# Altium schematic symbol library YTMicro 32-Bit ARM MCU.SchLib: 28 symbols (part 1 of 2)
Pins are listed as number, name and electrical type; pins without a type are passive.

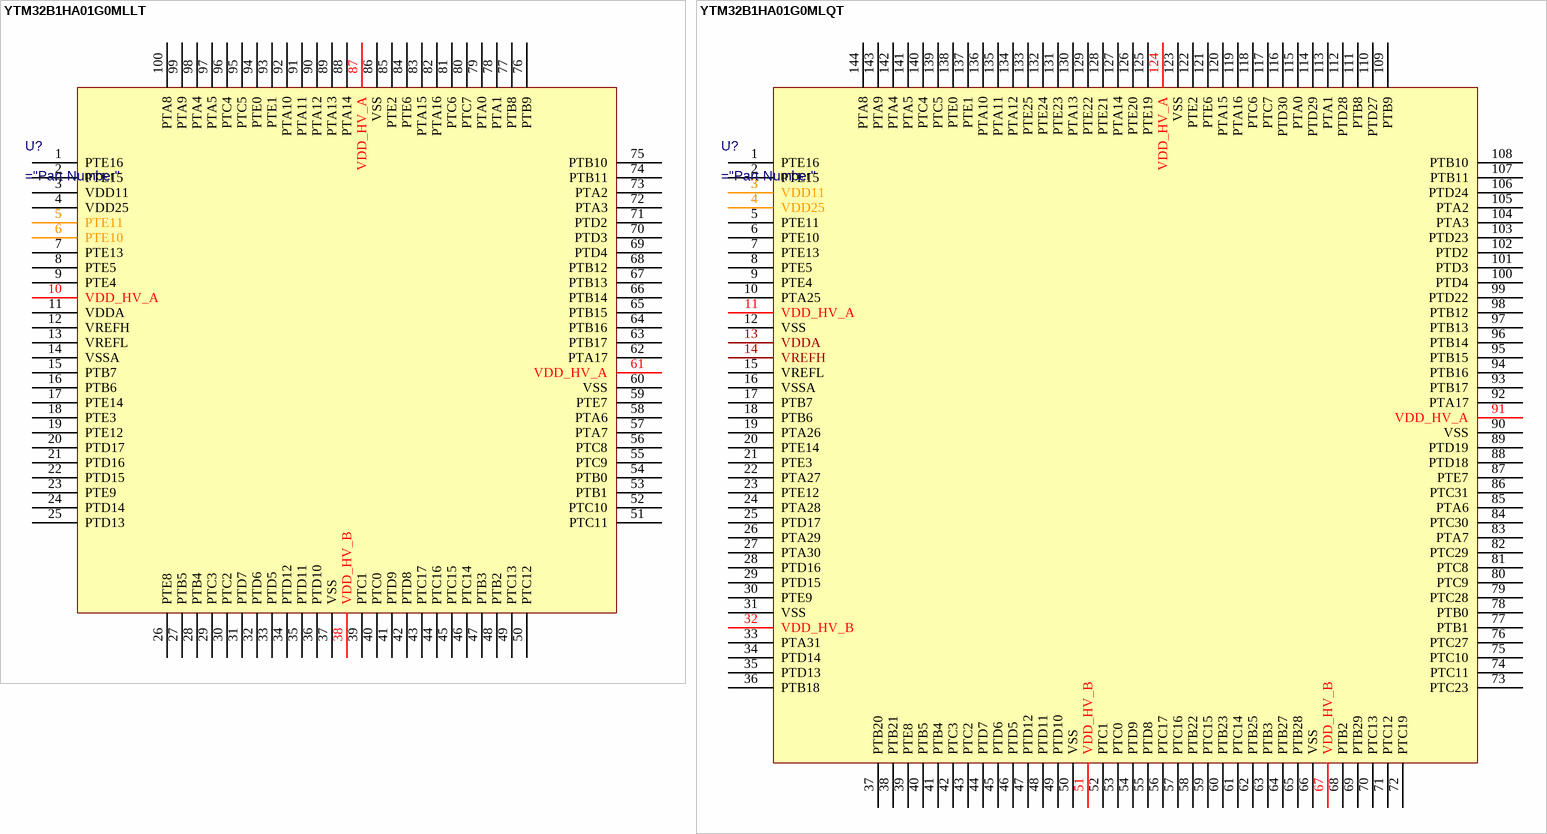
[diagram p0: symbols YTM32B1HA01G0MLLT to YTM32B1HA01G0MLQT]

## YTM32B1HA01G0MLLT
designator U?
B1H family  32-bit ARM Cortex-M7 MCU with Lockstep, 2M flash and 256K SRAM, LQFP-100 package
footprint LQFP100 14x14_M
pins: 1 PTE16, 2 PTE15, 3 VDD11, 4 VDD25, 5 PTE11, 6 PTE10, 7 PTE13, 8 PTE5, 9 PTE4, 10 VDD_HV_A, 11 VDDA, 12 VREFH, 13 VREFL, 14 VSSA, 15 PTB7, 16 PTB6, 17 PTE14, 18 PTE3, 19 PTE12, 20 PTD17, 21 PTD16, 22 PTD15, 23 PTE9, 24 PTD14, 25 PTD13, 26 PTE8, 27 PTB5, 28 PTB4, 29 PTC3, 30 PTC2, 31 PTD7, 32 PTD6, 33 PTD5, 34 PTD12, 35 PTD11, 36 PTD10, 37 VSS, 38 VDD_HV_B, 39 PTC1, 40 PTC0, 41 PTD9, 42 PTD8, 43 PTC17, 44 PTC16, 45 PTC15, 46 PTC14, 47 PTB3, 48 PTB2, 49 PTC13, 50 PTC12, 51 PTC11, 52 PTC10, 53 PTB1, 54 PTB0, 55 PTC9, 56 PTC8, 57 PTA7, 58 PTA6, 59 PTE7, 60 VSS, 61 VDD_HV_A, 62 PTA17, 63 PTB17, 64 PTB16, 65 PTB15, 66 PTB14, 67 PTB13, 68 PTB12, 69 PTD4, 70 PTD3, 71 PTD2, 72 PTA3, 73 PTA2, 74 PTB11, 75 PTB10, 76 PTB9, 77 PTB8, 78 PTA1, 79 PTA0, 80 PTC7, 81 PTC6, 82 PTA16, 83 PTA15, 84 PTE6, 85 PTE2, 86 VSS, 87 VDD_HV_A, 88 PTA14, 89 PTA13, 90 PTA12, 91 PTA11, 92 PTA10, 93 PTE1, 94 PTE0, 95 PTC5, 96 PTC4, 97 PTA5, 98 PTA4, 99 PTA9, 100 PTA8

## YTM32B1HA01G0MLQT
designator U?
B1H family  32-bit ARM Cortex-M7 MCU with Lockstep, 2M flash and 256K SRAM, LQFP-144 package
footprint LQFP144 (144-Pin Thin Quad Flat Pack 0.5 mm Pitch, IPC Medium Density)
pins: 1 PTE16, 2 PTE15, 3 VDD11, 4 VDD25, 5 PTE11, 6 PTE10, 7 PTE13, 8 PTE5, 9 PTE4, 10 PTA25, 11 VDD_HV_A, 12 VSS, 13 VDDA, 14 VREFH, 15 VREFL, 16 VSSA, 17 PTB7, 18 PTB6, 19 PTA26, 20 PTE14, 21 PTE3, 22 PTA27, 23 PTE12, 24 PTA28, 25 PTD17, 26 PTA29, 27 PTA30, 28 PTD16, 29 PTD15, 30 PTE9, 31 VSS, 32 VDD_HV_B, 33 PTA31, 34 PTD14, 35 PTD13, 36 PTB18, 37 PTB20, 38 PTB21, 39 PTE8, 40 PTB5, 41 PTB4, 42 PTC3, 43 PTC2, 44 PTD7, 45 PTD6, 46 PTD5, 47 PTD12, 48 PTD11, 49 PTD10, 50 VSS, 51 VDD_HV_B, 52 PTC1, 53 PTC0, 54 PTD9, 55 PTD8, 56 PTC17, 57 PTC16, 58 PTB22, 59 PTC15, 60 PTB23, 61 PTC14, 62 PTB25, 63 PTB3, 64 PTB27, 65 PTB28, 66 VSS, 67 VDD_HV_B, 68 PTB2, 69 PTB29, 70 PTC13, 71 PTC12, 72 PTC19, 73 PTC23, 74 PTC11, 75 PTC10, 76 PTC27, 77 PTB1, 78 PTB0, 79 PTC28, 80 PTC9, 81 PTC8, 82 PTC29, 83 PTA7, 84 PTC30, 85 PTA6, 86 PTC31, 87 PTE7, 88 PTD18, 89 PTD19, 90 VSS, 91 VDD_HV_A, 92 PTA17, 93 PTB17, 94 PTB16, 95 PTB15, 96 PTB14, 97 PTB13, 98 PTB12, 99 PTD22, 100 PTD4, 101 PTD3, 102 PTD2, 103 PTD23, 104 PTA3, 105 PTA2, 106 PTD24, 107 PTB11, 108 PTB10, 109 PTB9, 110 PTD27, 111 PTB8, 112 PTD28, 113 PTA1, 114 PTD29, 115 PTA0, 116 PTD30, 117 PTC7, 118 PTC6, 119 PTA16, 120 PTA15, 121 PTE6, 122 PTE2, 123 VSS, 124 VDD_HV_A, 125 PTE19, 126 PTE20, 127 PTA14, 128 PTE21, 129 PTE22, 130 PTA13, 131 PTE23, 132 PTE24, 133 PTE25, 134 PTA12, 135 PTA11, 136 PTA10, 137 PTE1, 138 PTE0, 139 PTC5, 140 PTC4, 141 PTA5, 142 PTA4, 143 PTA9, 144 PTA8

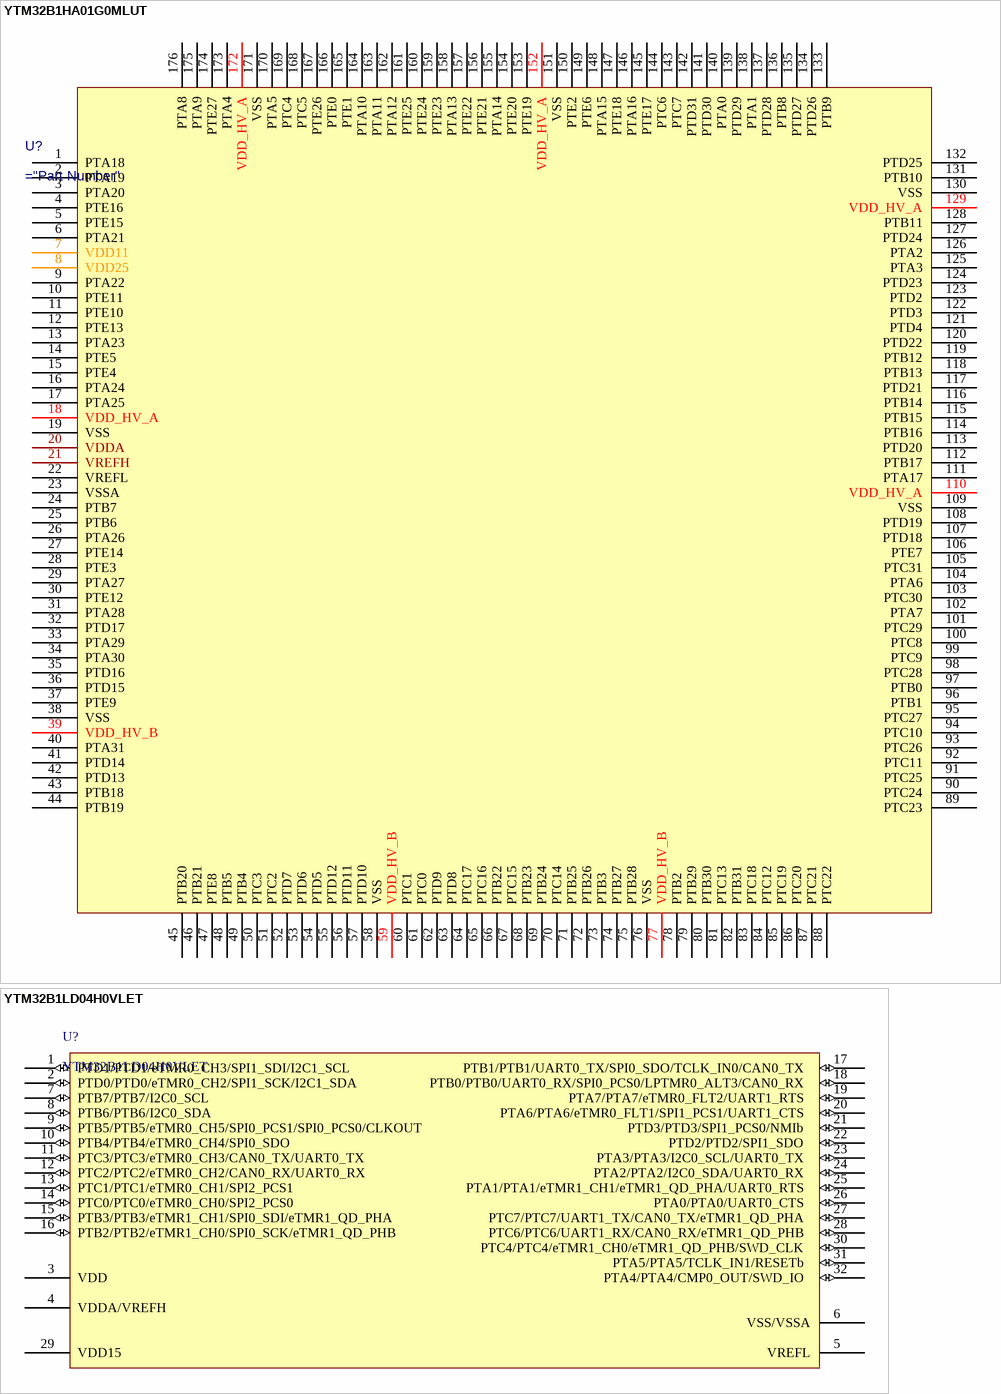
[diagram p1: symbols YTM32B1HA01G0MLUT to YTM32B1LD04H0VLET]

## YTM32B1HA01G0MLUT
designator U?
B1H family  32-bit ARM Cortex-M7 MCU with Lockstep, 2M flash and 256K SRAM, LQFP-176 package
footprint LQFP_176 (LQFP, 176-Leads, Body 26.4x26.4mm (max), Pitch 0.50mm, IPC Medium Density)
pins: 1 PTA18, 2 PTA19, 3 PTA20, 4 PTE16, 5 PTE15, 6 PTA21, 7 VDD11, 8 VDD25, 9 PTA22, 10 PTE11, 11 PTE10, 12 PTE13, 13 PTA23, 14 PTE5, 15 PTE4, 16 PTA24, 17 PTA25, 18 VDD_HV_A, 19 VSS, 20 VDDA, 21 VREFH, 22 VREFL, 23 VSSA, 24 PTB7, 25 PTB6, 26 PTA26, 27 PTE14, 28 PTE3, 29 PTA27, 30 PTE12, 31 PTA28, 32 PTD17, 33 PTA29, 34 PTA30, 35 PTD16, 36 PTD15, 37 PTE9, 38 VSS, 39 VDD_HV_B, 40 PTA31, 41 PTD14, 42 PTD13, 43 PTB18, 44 PTB19, 45 PTB20, 46 PTB21, 47 PTE8, 48 PTB5, 49 PTB4, 50 PTC3, 51 PTC2, 52 PTD7, 53 PTD6, 54 PTD5, 55 PTD12, 56 PTD11, 57 PTD10, 58 VSS, 59 VDD_HV_B, 60 PTC1, 61 PTC0, 62 PTD9, 63 PTD8, 64 PTC17, 65 PTC16, 66 PTB22, 67 PTC15, 68 PTB23, 69 PTB24, 70 PTC14, 71 PTB25, 72 PTB26, 73 PTB3, 74 PTB27, 75 PTB28, 76 VSS, 77 VDD_HV_B, 78 PTB2, 79 PTB29, 80 PTB30, 81 PTC13, 82 PTB31, 83 PTC18, 84 PTC12, 85 PTC19, 86 PTC20, 87 PTC21, 88 PTC22, 89 PTC23, 90 PTC24, 91 PTC25, 92 PTC11, 93 PTC26, 94 PTC10, 95 PTC27, 96 PTB1, 97 PTB0, 98 PTC28, 99 PTC9, 100 PTC8, 101 PTC29, 102 PTA7, 103 PTC30, 104 PTA6, 105 PTC31, 106 PTE7, 107 PTD18, 108 PTD19, 109 VSS, 110 VDD_HV_A, 111 PTA17, 112 PTB17, 113 PTD20, 114 PTB16, 115 PTB15, 116 PTB14, 117 PTD21, 118 PTB13, 119 PTB12, 120 PTD22, 121 PTD4, 122 PTD3, 123 PTD2, 124 PTD23, 125 PTA3, 126 PTA2, 127 PTD24, 128 PTB11, 129 VDD_HV_A, 130 VSS, 131 PTB10, 132 PTD25, 133 PTB9, 134 PTD26, 135 PTD27, 136 PTB8, 137 PTD28, 138 PTA1, 139 PTD29, 140 PTA0, 141 PTD30, 142 PTD31, 143 PTC7, 144 PTC6, 145 PTE17, 146 PTA16, 147 PTE18, 148 PTA15, 149 PTE6, 150 PTE2, 151 VSS, 152 VDD_HV_A, 153 PTE19, 154 PTE20, 155 PTA14, 156 PTE21, 157 PTE22, 158 PTA13, 159 PTE23, 160 PTE24, 161 PTE25, 162 PTA12, 163 PTA11, 164 PTA10, 165 PTE1, 166 PTE0, 167 PTE26, 168 PTC5, 169 PTC4, 170 PTA5, 171 VSS, 172 VDD_HV_A, 173 PTA4, 174 PTE27, 175 PTA9, 176 PTA8

## YTM32B1LD04H0VLET
designator U?
B1L family  32-bit ARM Cortex-M0+ MCU with 64K flash and 8K SRAM, LQFP-32 package
footprint LQFP32 7X7_L
footprint LQFP32 7X7_M
footprint LQFP32 7X7_N
pins: 1 PTD1/PTD1/eTMR0_CH3/SPI1_SDI/I2C1_SCL   (io), 2 PTD0/PTD0/eTMR0_CH2/SPI1_SCK/I2C1_SDA   (io), 3 VDD (power), 4 VDDA/VREFH (power), 5 VREFL (power), 6 VSS/VSSA (power), 7 PTB7/PTB7/I2C0_SCL  (io), 8 PTB6/PTB6/I2C0_SDA   (io), 9 PTB5/PTB5/eTMR0_CH5/SPI0_PCS1/SPI0_PCS0/CLKOUT   (io), 10 PTB4/PTB4/eTMR0_CH4/SPI0_SDO   (io), 11 PTC3/PTC3/eTMR0_CH3/CAN0_TX/UART0_TX   (io), 12 PTC2/PTC2/eTMR0_CH2/CAN0_RX/UART0_RX   (io), 13 PTC1/PTC1/eTMR0_CH1/SPI2_PCS1   (io), 14 PTC0/PTC0/eTMR0_CH0/SPI2_PCS0   (io), 15 PTB3/PTB3/eTMR1_CH1/SPI0_SDI/eTMR1_QD_PHA   (io), 16 PTB2/PTB2/eTMR1_CH0/SPI0_SCK/eTMR1_QD_PHB   (io), 17 PTB1/PTB1/UART0_TX/SPI0_SDO/TCLK_IN0/CAN0_TX   (io), 18 PTB0/PTB0/UART0_RX/SPI0_PCS0/LPTMR0_ALT3/CAN0_RX   (io), 19 PTA7/PTA7/eTMR0_FLT2/UART1_RTS   (io), 20 PTA6/PTA6/eTMR0_FLT1/SPI1_PCS1/UART1_CTS   (io), 21 PTD3/PTD3/SPI1_PCS0/NMIb   (io), 22 PTD2/PTD2/SPI1_SDO   (io), 23 PTA3/PTA3/I2C0_SCL/UART0_TX   (io), 24 PTA2/PTA2/I2C0_SDA/UART0_RX   (io), 25 PTA1/PTA1/eTMR1_CH1/eTMR1_QD_PHA/UART0_RTS   (io), 26 PTA0/PTA0/UART0_CTS   (io), 27 PTC7/PTC7/UART1_TX/CAN0_TX/eTMR1_QD_PHA   (io), 28 PTC6/PTC6/UART1_RX/CAN0_RX/eTMR1_QD_PHB   (io), 29 VDD15 (power), 30 PTC4/PTC4/eTMR1_CH0/eTMR1_QD_PHB/SWD_CLK   (io), 31 PTA5/PTA5/TCLK_IN1/RESETb   (io), 32 PTA4/PTA4/CMP0_OUT/SWD_IO   (io)

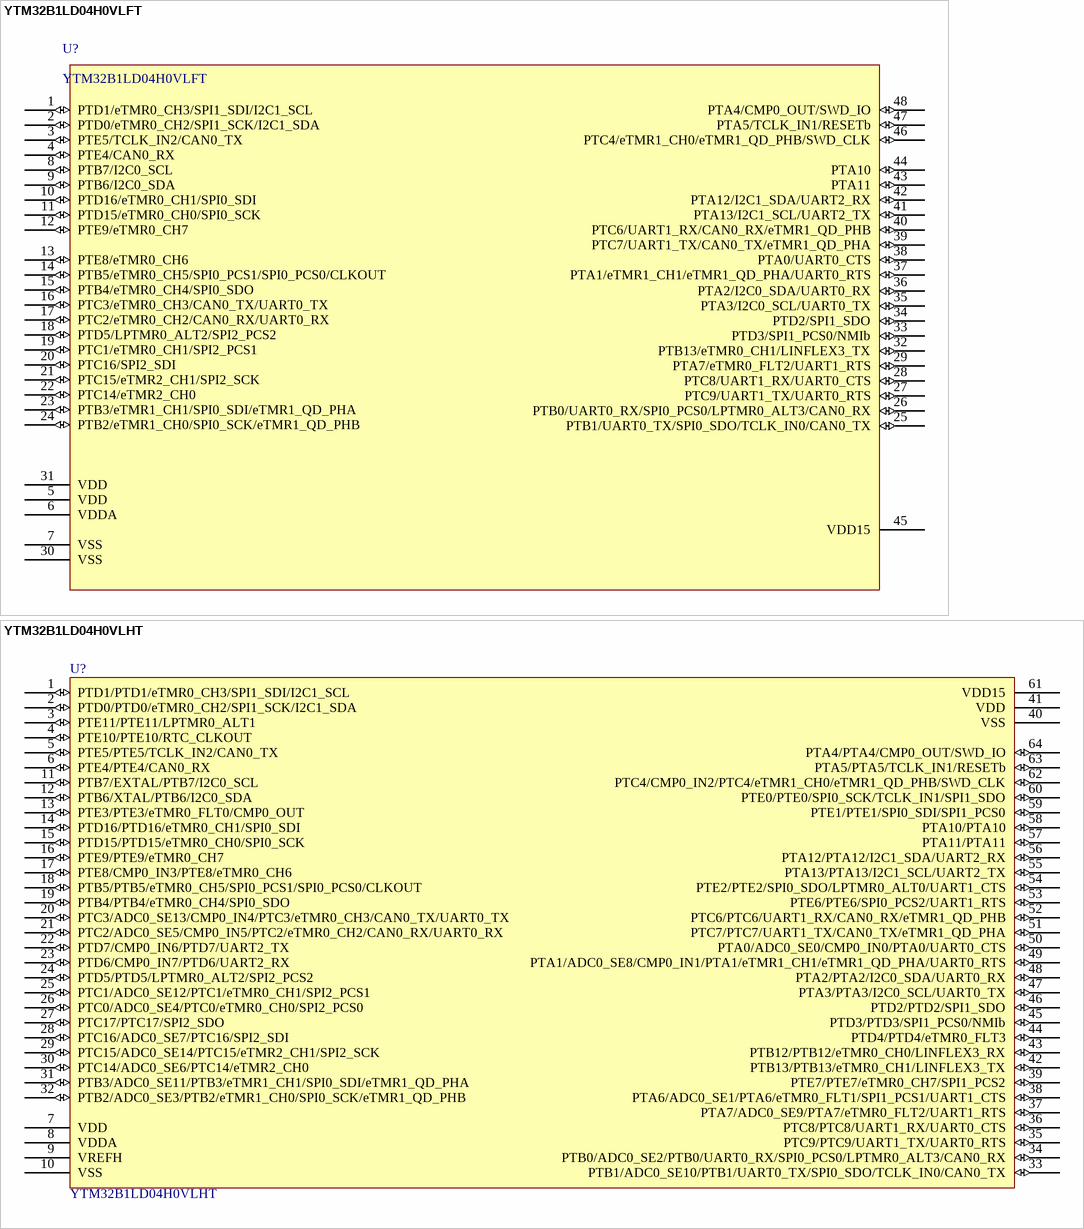
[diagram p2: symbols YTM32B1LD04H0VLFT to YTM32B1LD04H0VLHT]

## YTM32B1LD04H0VLFT
designator U?
B1L family  32-bit ARM Cortex-M0+ MCU with 64K flash and 8K SRAM, LQFP-48 package
footprint LQFP48 7X7_N (48脚，体宽7x7mm，脚距0.5mm)
footprint LQFP48 7X7_M
footprint LQFP48 7X7_L
pins: 1 PTD1/eTMR0_CH3/SPI1_SDI/I2C1_SCL (io), 2 PTD0/eTMR0_CH2/SPI1_SCK/I2C1_SDA (io), 3 PTE5/TCLK_IN2/CAN0_TX (io), 4 PTE4/CAN0_RX (io), 5 VDD (power), 6 VDDA (power), 7 VSS, 8 PTB7/I2C0_SCL (io), 9 PTB6/I2C0_SDA (io), 10 PTD16/eTMR0_CH1/SPI0_SDI (io), 11 PTD15/eTMR0_CH0/SPI0_SCK (io), 12 PTE9/eTMR0_CH7 (io), 13 PTE8/eTMR0_CH6 (io), 14 PTB5/eTMR0_CH5/SPI0_PCS1/SPI0_PCS0/CLKOUT (io), 15 PTB4/eTMR0_CH4/SPI0_SDO (io), 16 PTC3/eTMR0_CH3/CAN0_TX/UART0_TX (io), 17 PTC2/eTMR0_CH2/CAN0_RX/UART0_RX (io), 18 PTD5/LPTMR0_ALT2/SPI2_PCS2 (io), 19 PTC1/eTMR0_CH1/SPI2_PCS1 (io), 20 PTC16/SPI2_SDI (io), 21 PTC15/eTMR2_CH1/SPI2_SCK (io), 22 PTC14/eTMR2_CH0 (io), 23 PTB3/eTMR1_CH1/SPI0_SDI/eTMR1_QD_PHA (io), 24 PTB2/eTMR1_CH0/SPI0_SCK/eTMR1_QD_PHB (io), 25 PTB1/UART0_TX/SPI0_SDO/TCLK_IN0/CAN0_TX (io), 26 PTB0/UART0_RX/SPI0_PCS0/LPTMR0_ALT3/CAN0_RX (io), 27 PTC9/UART1_TX/UART0_RTS (io), 28 PTC8/UART1_RX/UART0_CTS (io), 29 PTA7/eTMR0_FLT2/UART1_RTS (io), 30 VSS, 31 VDD (power), 32 PTB13/eTMR0_CH1/LINFLEX3_TX (io), 33 PTD3/SPI1_PCS0/NMIb (io), 34 PTD2/SPI1_SDO (io), 35 PTA3/I2C0_SCL/UART0_TX (io), 36 PTA2/I2C0_SDA/UART0_RX (io), 37 PTA1/eTMR1_CH1/eTMR1_QD_PHA/UART0_RTS (io), 38 PTA0/UART0_CTS (io), 39 PTC7/UART1_TX/CAN0_TX/eTMR1_QD_PHA (io), 40 PTC6/UART1_RX/CAN0_RX/eTMR1_QD_PHB (io), 41 PTA13/I2C1_SCL/UART2_TX (io), 42 PTA12/I2C1_SDA/UART2_RX (io), 43 PTA11 (io), 44 PTA10 (io), 45 VDD15 (power), 46 PTC4/eTMR1_CH0/eTMR1_QD_PHB/SWD_CLK (io), 47 PTA5/TCLK_IN1/RESETb (io), 48 PTA4/CMP0_OUT/SWD_IO (io)

## YTM32B1LD04H0VLHT
designator U?
B1L family  32-bit ARM Cortex-M0+ MCU with 128K flash and 8K SRAM, LQFP-64 package
footprint LQFP64 10x10_N
footprint LQFP64 10x10_L
footprint LQFP64 10x10_M
pins: 1 PTD1/PTD1/eTMR0_CH3/SPI1_SDI/I2C1_SCL (io), 2 PTD0/PTD0/eTMR0_CH2/SPI1_SCK/I2C1_SDA (io), 3 PTE11/PTE11/LPTMR0_ALT1 (io), 4 PTE10/PTE10/RTC_CLKOUT (io), 5 PTE5/PTE5/TCLK_IN2/CAN0_TX (io), 6 PTE4/PTE4/CAN0_RX (io), 7 VDD (power), 8 VDDA (power), 9 VREFH (power), 10 VSS (power), 11 PTB7/EXTAL/PTB7/I2C0_SCL (io), 12 PTB6/XTAL/PTB6/I2C0_SDA (io), 13 PTE3/PTE3/eTMR0_FLT0/CMP0_OUT (io), 14 PTD16/PTD16/eTMR0_CH1/SPI0_SDI (io), 15 PTD15/PTD15/eTMR0_CH0/SPI0_SCK (io), 16 PTE9/PTE9/eTMR0_CH7 (io), 17 PTE8/CMP0_IN3/PTE8/eTMR0_CH6 (io), 18 PTB5/PTB5/eTMR0_CH5/SPI0_PCS1/SPI0_PCS0/CLKOUT (io), 19 PTB4/PTB4/eTMR0_CH4/SPI0_SDO (io), 20 PTC3/ADC0_SE13/CMP0_IN4/PTC3/eTMR0_CH3/CAN0_TX/UART0_TX (io), 21 PTC2/ADC0_SE5/CMP0_IN5/PTC2/eTMR0_CH2/CAN0_RX/UART0_RX (io), 22 PTD7/CMP0_IN6/PTD7/UART2_TX (io), 23 PTD6/CMP0_IN7/PTD6/UART2_RX (io), 24 PTD5/PTD5/LPTMR0_ALT2/SPI2_PCS2 (io), 25 PTC1/ADC0_SE12/PTC1/eTMR0_CH1/SPI2_PCS1 (io), 26 PTC0/ADC0_SE4/PTC0/eTMR0_CH0/SPI2_PCS0 (io), 27 PTC17/PTC17/SPI2_SDO (io), 28 PTC16/ADC0_SE7/PTC16/SPI2_SDI (io), 29 PTC15/ADC0_SE14/PTC15/eTMR2_CH1/SPI2_SCK (io), 30 PTC14/ADC0_SE6/PTC14/eTMR2_CH0 (io), 31 PTB3/ADC0_SE11/PTB3/eTMR1_CH1/SPI0_SDI/eTMR1_QD_PHA (io), 32 PTB2/ADC0_SE3/PTB2/eTMR1_CH0/SPI0_SCK/eTMR1_QD_PHB (io), 33 PTB1/ADC0_SE10/PTB1/UART0_TX/SPI0_SDO/TCLK_IN0/CAN0_TX (io), 34 PTB0/ADC0_SE2/PTB0/UART0_RX/SPI0_PCS0/LPTMR0_ALT3/CAN0_RX (io), 35 PTC9/PTC9/UART1_TX/UART0_RTS (io), 36 PTC8/PTC8/UART1_RX/UART0_CTS (io), 37 PTA7/ADC0_SE9/PTA7/eTMR0_FLT2/UART1_RTS (io), 38 PTA6/ADC0_SE1/PTA6/eTMR0_FLT1/SPI1_PCS1/UART1_CTS (io), 39 PTE7/PTE7/eTMR0_CH7/SPI1_PCS2 (io), 40 VSS (power), 41 VDD (power), 42 PTB13/PTB13/eTMR0_CH1/LINFLEX3_TX (io), 43 PTB12/PTB12/eTMR0_CH0/LINFLEX3_RX (io), 44 PTD4/PTD4/eTMR0_FLT3 (io), 45 PTD3/PTD3/SPI1_PCS0/NMIb (io), 46 PTD2/PTD2/SPI1_SDO (io), 47 PTA3/PTA3/I2C0_SCL/UART0_TX (io), 48 PTA2/PTA2/I2C0_SDA/UART0_RX (io), 49 PTA1/ADC0_SE8/CMP0_IN1/PTA1/eTMR1_CH1/eTMR1_QD_PHA/UART0_RTS (io), 50 PTA0/ADC0_SE0/CMP0_IN0/PTA0/UART0_CTS (io), 51 PTC7/PTC7/UART1_TX/CAN0_TX/eTMR1_QD_PHA (io), 52 PTC6/PTC6/UART1_RX/CAN0_RX/eTMR1_QD_PHB (io), 53 PTE6/PTE6/SPI0_PCS2/UART1_RTS (io), 54 PTE2/PTE2/SPI0_SDO/LPTMR0_ALT0/UART1_CTS (io), 55 PTA13/PTA13/I2C1_SCL/UART2_TX (io), 56 PTA12/PTA12/I2C1_SDA/UART2_RX (io), 57 PTA11/PTA11 (io), 58 PTA10/PTA10 (io), 59 PTE1/PTE1/SPI0_SDI/SPI1_PCS0 (io), 60 PTE0/PTE0/SPI0_SCK/TCLK_IN1/SPI1_SDO (io), 61 VDD15 (power), 62 PTC4/CMP0_IN2/PTC4/eTMR1_CH0/eTMR1_QD_PHB/SWD_CLK (io), 63 PTA5/PTA5/TCLK_IN1/RESETb (io), 64 PTA4/PTA4/CMP0_OUT/SWD_IO (io)

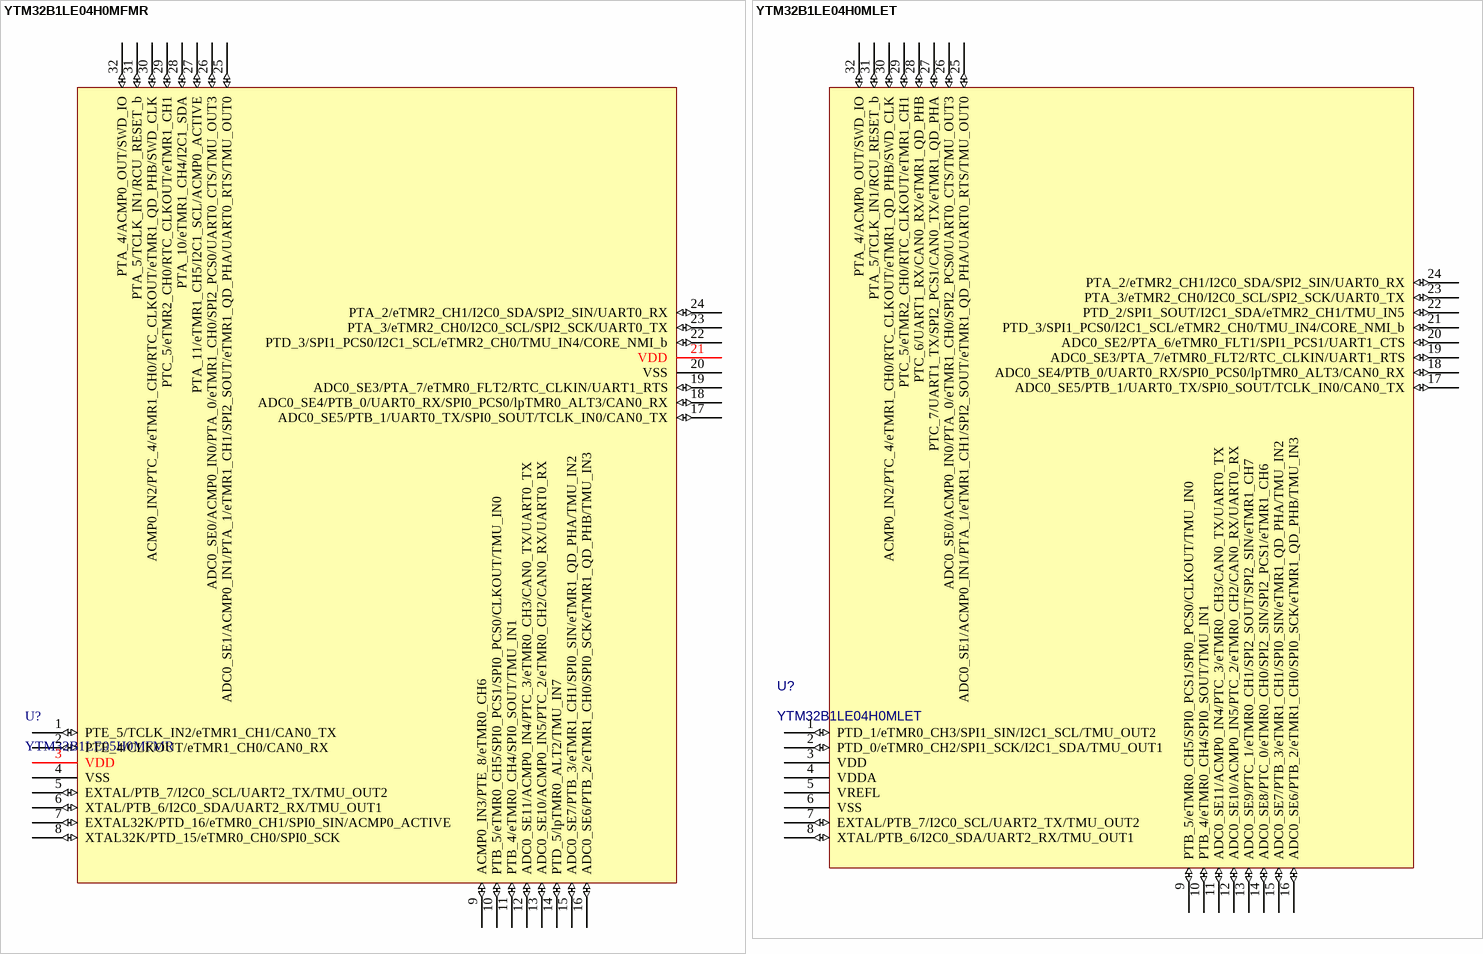
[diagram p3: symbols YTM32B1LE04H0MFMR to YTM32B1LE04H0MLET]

## YTM32B1LE04H0MFMR
designator U?, comment YTM32B1LE05H0MFMR
B1L family  32-bit ARM Cortex-M0+ MCU with 128K flash and 16K SRAM, QFN-32 package
footprint QFN32
pins: 1 PTE_5/TCLK_IN2/eTMR1_CH1/CAN0_TX (io), 2 PTE_4/CLKOUT/eTMR1_CH0/CAN0_RX (io), 3 VDD, 4 VSS, 5 EXTAL/PTB_7/I2C0_SCL/UART2_TX/TMU_OUT2 (io), 6 XTAL/PTB_6/I2C0_SDA/UART2_RX/TMU_OUT1 (io), 7 EXTAL32K/PTD_16/eTMR0_CH1/SPI0_SIN/ACMP0_ACTIVE (io), 8 XTAL32K/PTD_15/eTMR0_CH0/SPI0_SCK (io), 9 ACMP0_IN3/PTE_8/eTMR0_CH6 (io), 10 PTB_5/eTMR0_CH5/SPI0_PCS1/SPI0_PCS0/CLKOUT/TMU_IN0 (io), 11 PTB_4/eTMR0_CH4/SPI0_SOUT/TMU_IN1 (io), 12 ADC0_SE11/ACMP0_IN4/PTC_3/eTMR0_CH3/CAN0_TX/UART0_TX (io), 13 ADC0_SE10/ACMP0_IN5/PTC_2/eTMR0_CH2/CAN0_RX/UART0_RX (io), 14 PTD_5/lpTMR0_ALT2/TMU_IN7 (io), 15 ADC0_SE7/PTB_3/eTMR1_CH1/SPI0_SIN/eTMR1_QD_PHA/TMU_IN2 (io), 16 ADC0_SE6/PTB_2/eTMR1_CH0/SPI0_SCK/eTMR1_QD_PHB/TMU_IN3 (io), 17 ADC0_SE5/PTB_1/UART0_TX/SPI0_SOUT/TCLK_IN0/CAN0_TX (io), 18 ADC0_SE4/PTB_0/UART0_RX/SPI0_PCS0/lpTMR0_ALT3/CAN0_RX (io), 19 ADC0_SE3/PTA_7/eTMR0_FLT2/RTC_CLKIN/UART1_RTS (io), 20 VSS, 21 VDD, 22 PTD_3/SPI1_PCS0/I2C1_SCL/eTMR2_CH0/TMU_IN4/CORE_NMI_b (io), 23 PTA_3/eTMR2_CH0/I2C0_SCL/SPI2_SCK/UART0_TX (io), 24 PTA_2/eTMR2_CH1/I2C0_SDA/SPI2_SIN/UART0_RX (io), 25 ADC0_SE1/ACMP0_IN1/PTA_1/eTMR1_CH1/SPI2_SOUT/eTMR1_QD_PHA/UART0_RTS/TMU_OUT0 (io), 26 ADC0_SE0/ACMP0_IN0/PTA_0/eTMR1_CH0/SPI2_PCS0/UART0_CTS/TMU_OUT3 (io), 27 PTA_11/eTMR1_CH5/I2C1_SCL/ACMP0_ACTIVE (io), 28 PTA_10/eTMR1_CH4/I2C1_SDA (io), 29 PTC_5/eTMR2_CH0/RTC_CLKOUT/eTMR1_CH1 (io), 30 ACMP0_IN2/PTC_4/eTMR1_CH0/RTC_CLKOUT/eTMR1_QD_PHB/SWD_CLK (io), 31 PTA_5/TCLK_IN1/RCU_RESET_b (io), 32 PTA_4/ACMP0_OUT/SWD_IO (io)

## YTM32B1LE04H0MLET
designator U?
B1L family  32-bit ARM Cortex-M0+ MCU with 128K flash and 16K SRAM, LQFP-32 package
footprint LQFP32 7X7_L
footprint LQFP32 7X7_M
footprint LQFP32 7X7_N
pins: 1 PTD_1/eTMR0_CH3/SPI1_SIN/I2C1_SCL/TMU_OUT2 (io), 2 PTD_0/eTMR0_CH2/SPI1_SCK/I2C1_SDA/TMU_OUT1 (io), 3 VDD, 4 VDDA, 5 VREFL, 6 VSS, 7 EXTAL/PTB_7/I2C0_SCL/UART2_TX/TMU_OUT2 (io), 8 XTAL/PTB_6/I2C0_SDA/UART2_RX/TMU_OUT1 (io), 9 PTB_5/eTMR0_CH5/SPI0_PCS1/SPI0_PCS0/CLKOUT/TMU_IN0 (io), 10 PTB_4/eTMR0_CH4/SPI0_SOUT/TMU_IN1 (io), 11 ADC0_SE11/ACMP0_IN4/PTC_3/eTMR0_CH3/CAN0_TX/UART0_TX (io), 12 ADC0_SE10/ACMP0_IN5/PTC_2/eTMR0_CH2/CAN0_RX/UART0_RX (io), 13 ADC0_SE9/PTC_1/eTMR0_CH1/SPI2_SOUT/SPI2_SIN/eTMR1_CH7 (io), 14 ADC0_SE8/PTC_0/eTMR0_CH0/SPI2_SIN/SPI2_PCS1/eTMR1_CH6 (io), 15 ADC0_SE7/PTB_3/eTMR1_CH1/SPI0_SIN/eTMR1_QD_PHA/TMU_IN2 (io), 16 ADC0_SE6/PTB_2/eTMR1_CH0/SPI0_SCK/eTMR1_QD_PHB/TMU_IN3 (io), 17 ADC0_SE5/PTB_1/UART0_TX/SPI0_SOUT/TCLK_IN0/CAN0_TX (io), 18 ADC0_SE4/PTB_0/UART0_RX/SPI0_PCS0/lpTMR0_ALT3/CAN0_RX (io), 19 ADC0_SE3/PTA_7/eTMR0_FLT2/RTC_CLKIN/UART1_RTS (io), 20 ADC0_SE2/PTA_6/eTMR0_FLT1/SPI1_PCS1/UART1_CTS (io), 21 PTD_3/SPI1_PCS0/I2C1_SCL/eTMR2_CH0/TMU_IN4/CORE_NMI_b (io), 22 PTD_2/SPI1_SOUT/I2C1_SDA/eTMR2_CH1/TMU_IN5 (io), 23 PTA_3/eTMR2_CH0/I2C0_SCL/SPI2_SCK/UART0_TX (io), 24 PTA_2/eTMR2_CH1/I2C0_SDA/SPI2_SIN/UART0_RX (io), 25 ADC0_SE1/ACMP0_IN1/PTA_1/eTMR1_CH1/SPI2_SOUT/eTMR1_QD_PHA/UART0_RTS/TMU_OUT0 (io), 26 ADC0_SE0/ACMP0_IN0/PTA_0/eTMR1_CH0/SPI2_PCS0/UART0_CTS/TMU_OUT3 (io), 27 PTC_7/UART1_TX/SPI2_PCS1/CAN0_TX/eTMR1_QD_PHA (io), 28 PTC_6/UART1_RX/CAN0_RX/eTMR1_QD_PHB (io), 29 PTC_5/eTMR2_CH0/RTC_CLKOUT/eTMR1_CH1 (io), 30 ACMP0_IN2/PTC_4/eTMR1_CH0/RTC_CLKOUT/eTMR1_QD_PHB/SWD_CLK (io), 31 PTA_5/TCLK_IN1/RCU_RESET_b (io), 32 PTA_4/ACMP0_OUT/SWD_IO (io)

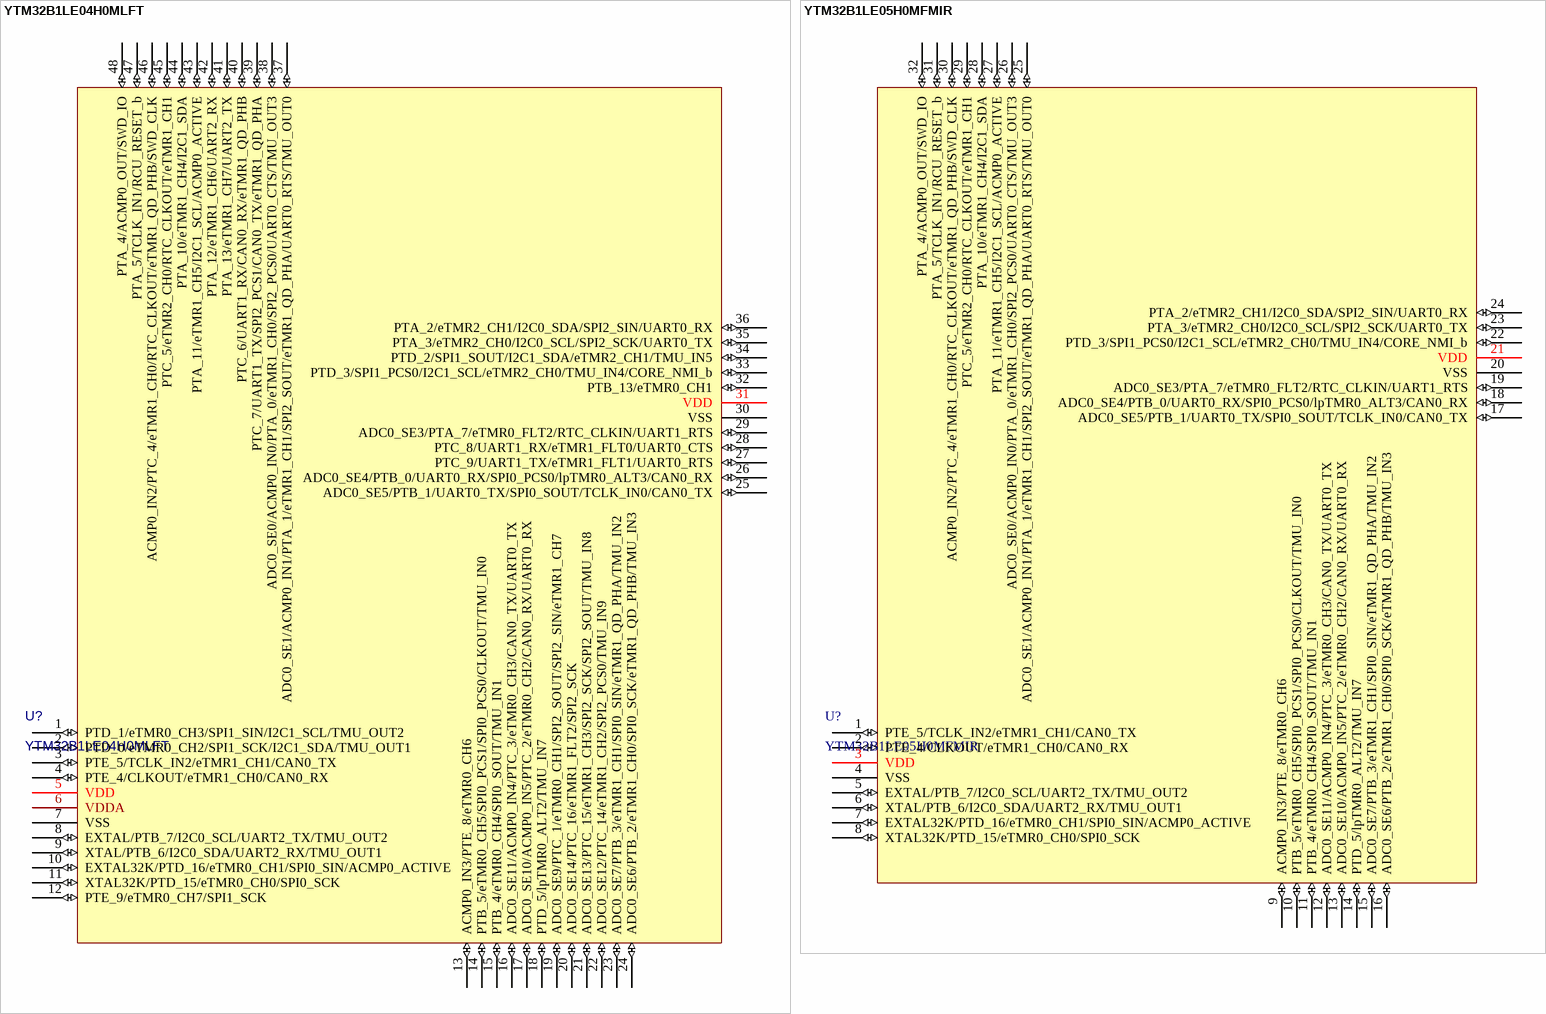
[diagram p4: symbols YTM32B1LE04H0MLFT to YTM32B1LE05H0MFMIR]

## YTM32B1LE04H0MLFT
designator U?
B1L family  32-bit ARM Cortex-M0+ MCU with 128K flash and 16K SRAM, LQFP-48 package
footprint LQFP48 7X7_L
footprint LQFP48 7X7_M
footprint LQFP48 7X7_N
pins: 1 PTD_1/eTMR0_CH3/SPI1_SIN/I2C1_SCL/TMU_OUT2 (io), 2 PTD_0/eTMR0_CH2/SPI1_SCK/I2C1_SDA/TMU_OUT1 (io), 3 PTE_5/TCLK_IN2/eTMR1_CH1/CAN0_TX (io), 4 PTE_4/CLKOUT/eTMR1_CH0/CAN0_RX (io), 5 VDD, 6 VDDA, 7 VSS, 8 EXTAL/PTB_7/I2C0_SCL/UART2_TX/TMU_OUT2 (io), 9 XTAL/PTB_6/I2C0_SDA/UART2_RX/TMU_OUT1 (io), 10 EXTAL32K/PTD_16/eTMR0_CH1/SPI0_SIN/ACMP0_ACTIVE (io), 11 XTAL32K/PTD_15/eTMR0_CH0/SPI0_SCK (io), 12 PTE_9/eTMR0_CH7/SPI1_SCK (io), 13 ACMP0_IN3/PTE_8/eTMR0_CH6 (io), 14 PTB_5/eTMR0_CH5/SPI0_PCS1/SPI0_PCS0/CLKOUT/TMU_IN0 (io), 15 PTB_4/eTMR0_CH4/SPI0_SOUT/TMU_IN1 (io), 16 ADC0_SE11/ACMP0_IN4/PTC_3/eTMR0_CH3/CAN0_TX/UART0_TX (io), 17 ADC0_SE10/ACMP0_IN5/PTC_2/eTMR0_CH2/CAN0_RX/UART0_RX (io), 18 PTD_5/lpTMR0_ALT2/TMU_IN7 (io), 19 ADC0_SE9/PTC_1/eTMR0_CH1/SPI2_SOUT/SPI2_SIN/eTMR1_CH7 (io), 20 ADC0_SE14/PTC_16/eTMR1_FLT2/SPI2_SCK (io), 21 ADC0_SE13/PTC_15/eTMR1_CH3/SPI2_SCK/SPI2_SOUT/TMU_IN8 (io), 22 ADC0_SE12/PTC_14/eTMR1_CH2/SPI2_PCS0/TMU_IN9 (io), 23 ADC0_SE7/PTB_3/eTMR1_CH1/SPI0_SIN/eTMR1_QD_PHA/TMU_IN2 (io), 24 ADC0_SE6/PTB_2/eTMR1_CH0/SPI0_SCK/eTMR1_QD_PHB/TMU_IN3 (io), 25 ADC0_SE5/PTB_1/UART0_TX/SPI0_SOUT/TCLK_IN0/CAN0_TX (io), 26 ADC0_SE4/PTB_0/UART0_RX/SPI0_PCS0/lpTMR0_ALT3/CAN0_RX (io), 27 PTC_9/UART1_TX/eTMR1_FLT1/UART0_RTS (io), 28 PTC_8/UART1_RX/eTMR1_FLT0/UART0_CTS (io), 29 ADC0_SE3/PTA_7/eTMR0_FLT2/RTC_CLKIN/UART1_RTS (io), 30 VSS, 31 VDD, 32 PTB_13/eTMR0_CH1 (io), 33 PTD_3/SPI1_PCS0/I2C1_SCL/eTMR2_CH0/TMU_IN4/CORE_NMI_b (io), 34 PTD_2/SPI1_SOUT/I2C1_SDA/eTMR2_CH1/TMU_IN5 (io), 35 PTA_3/eTMR2_CH0/I2C0_SCL/SPI2_SCK/UART0_TX (io), 36 PTA_2/eTMR2_CH1/I2C0_SDA/SPI2_SIN/UART0_RX (io), 37 ADC0_SE1/ACMP0_IN1/PTA_1/eTMR1_CH1/SPI2_SOUT/eTMR1_QD_PHA/UART0_RTS/TMU_OUT0 (io), 38 ADC0_SE0/ACMP0_IN0/PTA_0/eTMR1_CH0/SPI2_PCS0/UART0_CTS/TMU_OUT3 (io), 39 PTC_7/UART1_TX/SPI2_PCS1/CAN0_TX/eTMR1_QD_PHA (io), 40 PTC_6/UART1_RX/CAN0_RX/eTMR1_QD_PHB (io), 41 PTA_13/eTMR1_CH7/UART2_TX (io), 42 PTA_12/eTMR1_CH6/UART2_RX (io), 43 PTA_11/eTMR1_CH5/I2C1_SCL/ACMP0_ACTIVE (io), 44 PTA_10/eTMR1_CH4/I2C1_SDA (io), 45 PTC_5/eTMR2_CH0/RTC_CLKOUT/eTMR1_CH1 (io), 46 ACMP0_IN2/PTC_4/eTMR1_CH0/RTC_CLKOUT/eTMR1_QD_PHB/SWD_CLK (io), 47 PTA_5/TCLK_IN1/RCU_RESET_b (io), 48 PTA_4/ACMP0_OUT/SWD_IO (io)

## YTM32B1LE05H0MFMIR
designator U?
B1L family  32-bit ARM Cortex-M0+ MCU with 128K flash and 16K SRAM, QFN-32 package, with ISELED support
footprint QFN32
pins: 1 PTE_5/TCLK_IN2/eTMR1_CH1/CAN0_TX (io), 2 PTE_4/CLKOUT/eTMR1_CH0/CAN0_RX (io), 3 VDD, 4 VSS, 5 EXTAL/PTB_7/I2C0_SCL/UART2_TX/TMU_OUT2 (io), 6 XTAL/PTB_6/I2C0_SDA/UART2_RX/TMU_OUT1 (io), 7 EXTAL32K/PTD_16/eTMR0_CH1/SPI0_SIN/ACMP0_ACTIVE (io), 8 XTAL32K/PTD_15/eTMR0_CH0/SPI0_SCK (io), 9 ACMP0_IN3/PTE_8/eTMR0_CH6 (io), 10 PTB_5/eTMR0_CH5/SPI0_PCS1/SPI0_PCS0/CLKOUT/TMU_IN0 (io), 11 PTB_4/eTMR0_CH4/SPI0_SOUT/TMU_IN1 (io), 12 ADC0_SE11/ACMP0_IN4/PTC_3/eTMR0_CH3/CAN0_TX/UART0_TX (io), 13 ADC0_SE10/ACMP0_IN5/PTC_2/eTMR0_CH2/CAN0_RX/UART0_RX (io), 14 PTD_5/lpTMR0_ALT2/TMU_IN7 (io), 15 ADC0_SE7/PTB_3/eTMR1_CH1/SPI0_SIN/eTMR1_QD_PHA/TMU_IN2 (io), 16 ADC0_SE6/PTB_2/eTMR1_CH0/SPI0_SCK/eTMR1_QD_PHB/TMU_IN3 (io), 17 ADC0_SE5/PTB_1/UART0_TX/SPI0_SOUT/TCLK_IN0/CAN0_TX (io), 18 ADC0_SE4/PTB_0/UART0_RX/SPI0_PCS0/lpTMR0_ALT3/CAN0_RX (io), 19 ADC0_SE3/PTA_7/eTMR0_FLT2/RTC_CLKIN/UART1_RTS (io), 20 VSS, 21 VDD, 22 PTD_3/SPI1_PCS0/I2C1_SCL/eTMR2_CH0/TMU_IN4/CORE_NMI_b (io), 23 PTA_3/eTMR2_CH0/I2C0_SCL/SPI2_SCK/UART0_TX (io), 24 PTA_2/eTMR2_CH1/I2C0_SDA/SPI2_SIN/UART0_RX (io), 25 ADC0_SE1/ACMP0_IN1/PTA_1/eTMR1_CH1/SPI2_SOUT/eTMR1_QD_PHA/UART0_RTS/TMU_OUT0 (io), 26 ADC0_SE0/ACMP0_IN0/PTA_0/eTMR1_CH0/SPI2_PCS0/UART0_CTS/TMU_OUT3 (io), 27 PTA_11/eTMR1_CH5/I2C1_SCL/ACMP0_ACTIVE (io), 28 PTA_10/eTMR1_CH4/I2C1_SDA (io), 29 PTC_5/eTMR2_CH0/RTC_CLKOUT/eTMR1_CH1 (io), 30 ACMP0_IN2/PTC_4/eTMR1_CH0/RTC_CLKOUT/eTMR1_QD_PHB/SWD_CLK (io), 31 PTA_5/TCLK_IN1/RCU_RESET_b (io), 32 PTA_4/ACMP0_OUT/SWD_IO (io)

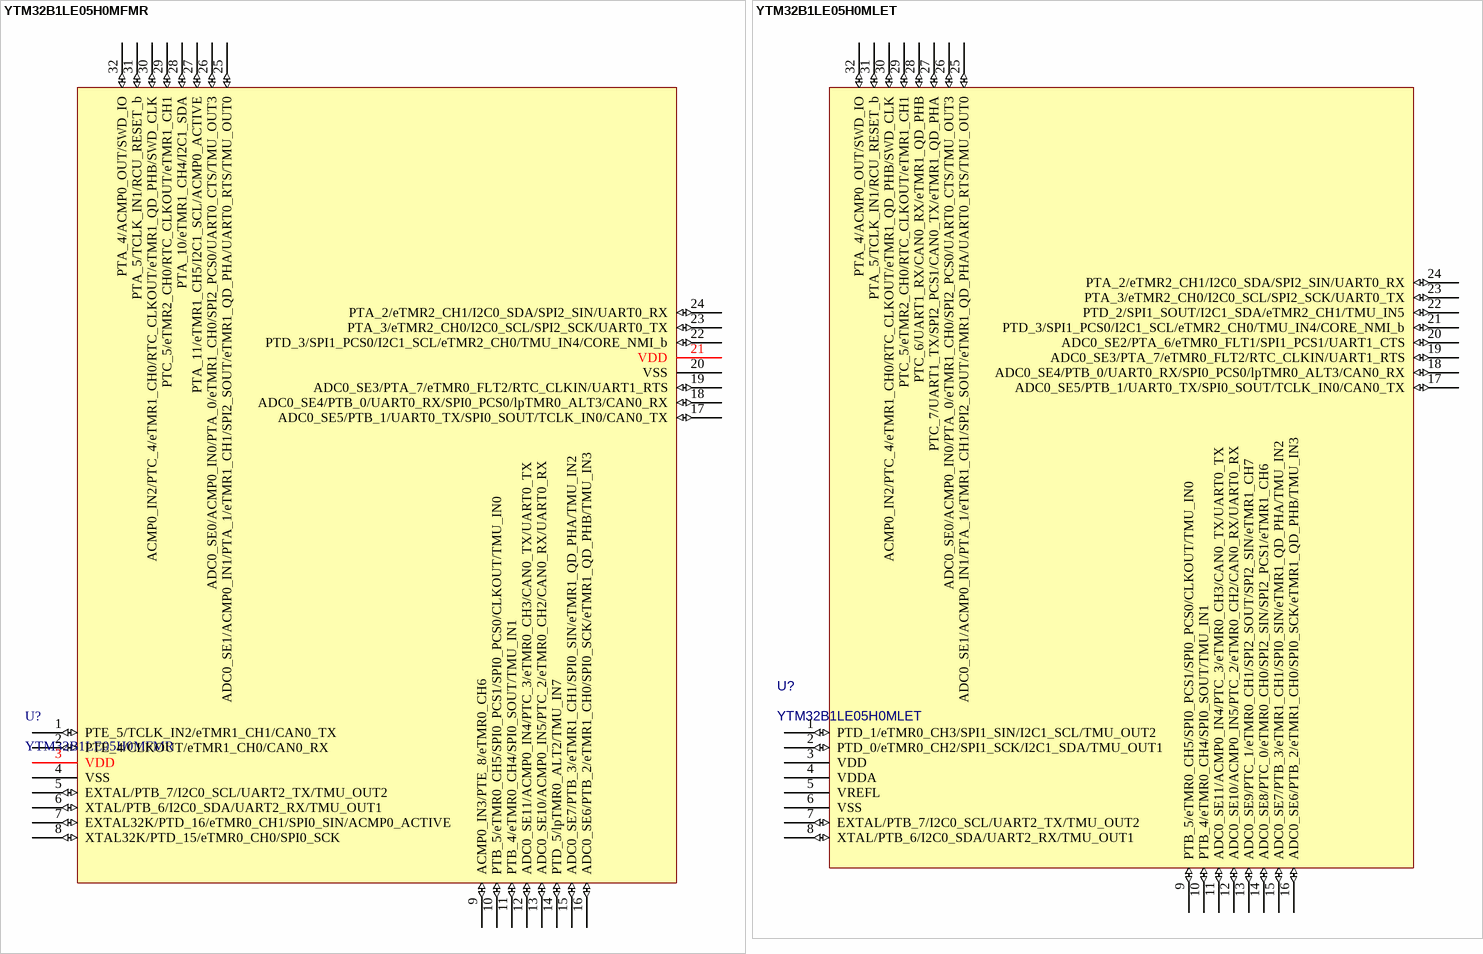
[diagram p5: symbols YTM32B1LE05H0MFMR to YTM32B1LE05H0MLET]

## YTM32B1LE05H0MFMR
designator U?
B1L family  32-bit ARM Cortex-M0+ MCU with 128K flash and 16K SRAM, QFN-32 package
footprint QFN32
pins: 1 PTE_5/TCLK_IN2/eTMR1_CH1/CAN0_TX (io), 2 PTE_4/CLKOUT/eTMR1_CH0/CAN0_RX (io), 3 VDD, 4 VSS, 5 EXTAL/PTB_7/I2C0_SCL/UART2_TX/TMU_OUT2 (io), 6 XTAL/PTB_6/I2C0_SDA/UART2_RX/TMU_OUT1 (io), 7 EXTAL32K/PTD_16/eTMR0_CH1/SPI0_SIN/ACMP0_ACTIVE (io), 8 XTAL32K/PTD_15/eTMR0_CH0/SPI0_SCK (io), 9 ACMP0_IN3/PTE_8/eTMR0_CH6 (io), 10 PTB_5/eTMR0_CH5/SPI0_PCS1/SPI0_PCS0/CLKOUT/TMU_IN0 (io), 11 PTB_4/eTMR0_CH4/SPI0_SOUT/TMU_IN1 (io), 12 ADC0_SE11/ACMP0_IN4/PTC_3/eTMR0_CH3/CAN0_TX/UART0_TX (io), 13 ADC0_SE10/ACMP0_IN5/PTC_2/eTMR0_CH2/CAN0_RX/UART0_RX (io), 14 PTD_5/lpTMR0_ALT2/TMU_IN7 (io), 15 ADC0_SE7/PTB_3/eTMR1_CH1/SPI0_SIN/eTMR1_QD_PHA/TMU_IN2 (io), 16 ADC0_SE6/PTB_2/eTMR1_CH0/SPI0_SCK/eTMR1_QD_PHB/TMU_IN3 (io), 17 ADC0_SE5/PTB_1/UART0_TX/SPI0_SOUT/TCLK_IN0/CAN0_TX (io), 18 ADC0_SE4/PTB_0/UART0_RX/SPI0_PCS0/lpTMR0_ALT3/CAN0_RX (io), 19 ADC0_SE3/PTA_7/eTMR0_FLT2/RTC_CLKIN/UART1_RTS (io), 20 VSS, 21 VDD, 22 PTD_3/SPI1_PCS0/I2C1_SCL/eTMR2_CH0/TMU_IN4/CORE_NMI_b (io), 23 PTA_3/eTMR2_CH0/I2C0_SCL/SPI2_SCK/UART0_TX (io), 24 PTA_2/eTMR2_CH1/I2C0_SDA/SPI2_SIN/UART0_RX (io), 25 ADC0_SE1/ACMP0_IN1/PTA_1/eTMR1_CH1/SPI2_SOUT/eTMR1_QD_PHA/UART0_RTS/TMU_OUT0 (io), 26 ADC0_SE0/ACMP0_IN0/PTA_0/eTMR1_CH0/SPI2_PCS0/UART0_CTS/TMU_OUT3 (io), 27 PTA_11/eTMR1_CH5/I2C1_SCL/ACMP0_ACTIVE (io), 28 PTA_10/eTMR1_CH4/I2C1_SDA (io), 29 PTC_5/eTMR2_CH0/RTC_CLKOUT/eTMR1_CH1 (io), 30 ACMP0_IN2/PTC_4/eTMR1_CH0/RTC_CLKOUT/eTMR1_QD_PHB/SWD_CLK (io), 31 PTA_5/TCLK_IN1/RCU_RESET_b (io), 32 PTA_4/ACMP0_OUT/SWD_IO (io)

## YTM32B1LE05H0MLET
designator U?
B1L family  32-bit ARM Cortex-M0+ MCU with 128K flash and 16K SRAM, LQFP-32 package
footprint LQFP32 7X7_L
footprint LQFP32 7X7_M
footprint LQFP32 7X7_N
pins: 1 PTD_1/eTMR0_CH3/SPI1_SIN/I2C1_SCL/TMU_OUT2 (io), 2 PTD_0/eTMR0_CH2/SPI1_SCK/I2C1_SDA/TMU_OUT1 (io), 3 VDD, 4 VDDA, 5 VREFL, 6 VSS, 7 EXTAL/PTB_7/I2C0_SCL/UART2_TX/TMU_OUT2 (io), 8 XTAL/PTB_6/I2C0_SDA/UART2_RX/TMU_OUT1 (io), 9 PTB_5/eTMR0_CH5/SPI0_PCS1/SPI0_PCS0/CLKOUT/TMU_IN0 (io), 10 PTB_4/eTMR0_CH4/SPI0_SOUT/TMU_IN1 (io), 11 ADC0_SE11/ACMP0_IN4/PTC_3/eTMR0_CH3/CAN0_TX/UART0_TX (io), 12 ADC0_SE10/ACMP0_IN5/PTC_2/eTMR0_CH2/CAN0_RX/UART0_RX (io), 13 ADC0_SE9/PTC_1/eTMR0_CH1/SPI2_SOUT/SPI2_SIN/eTMR1_CH7 (io), 14 ADC0_SE8/PTC_0/eTMR0_CH0/SPI2_SIN/SPI2_PCS1/eTMR1_CH6 (io), 15 ADC0_SE7/PTB_3/eTMR1_CH1/SPI0_SIN/eTMR1_QD_PHA/TMU_IN2 (io), 16 ADC0_SE6/PTB_2/eTMR1_CH0/SPI0_SCK/eTMR1_QD_PHB/TMU_IN3 (io), 17 ADC0_SE5/PTB_1/UART0_TX/SPI0_SOUT/TCLK_IN0/CAN0_TX (io), 18 ADC0_SE4/PTB_0/UART0_RX/SPI0_PCS0/lpTMR0_ALT3/CAN0_RX (io), 19 ADC0_SE3/PTA_7/eTMR0_FLT2/RTC_CLKIN/UART1_RTS (io), 20 ADC0_SE2/PTA_6/eTMR0_FLT1/SPI1_PCS1/UART1_CTS (io), 21 PTD_3/SPI1_PCS0/I2C1_SCL/eTMR2_CH0/TMU_IN4/CORE_NMI_b (io), 22 PTD_2/SPI1_SOUT/I2C1_SDA/eTMR2_CH1/TMU_IN5 (io), 23 PTA_3/eTMR2_CH0/I2C0_SCL/SPI2_SCK/UART0_TX (io), 24 PTA_2/eTMR2_CH1/I2C0_SDA/SPI2_SIN/UART0_RX (io), 25 ADC0_SE1/ACMP0_IN1/PTA_1/eTMR1_CH1/SPI2_SOUT/eTMR1_QD_PHA/UART0_RTS/TMU_OUT0 (io), 26 ADC0_SE0/ACMP0_IN0/PTA_0/eTMR1_CH0/SPI2_PCS0/UART0_CTS/TMU_OUT3 (io), 27 PTC_7/UART1_TX/SPI2_PCS1/CAN0_TX/eTMR1_QD_PHA (io), 28 PTC_6/UART1_RX/CAN0_RX/eTMR1_QD_PHB (io), 29 PTC_5/eTMR2_CH0/RTC_CLKOUT/eTMR1_CH1 (io), 30 ACMP0_IN2/PTC_4/eTMR1_CH0/RTC_CLKOUT/eTMR1_QD_PHB/SWD_CLK (io), 31 PTA_5/TCLK_IN1/RCU_RESET_b (io), 32 PTA_4/ACMP0_OUT/SWD_IO (io)

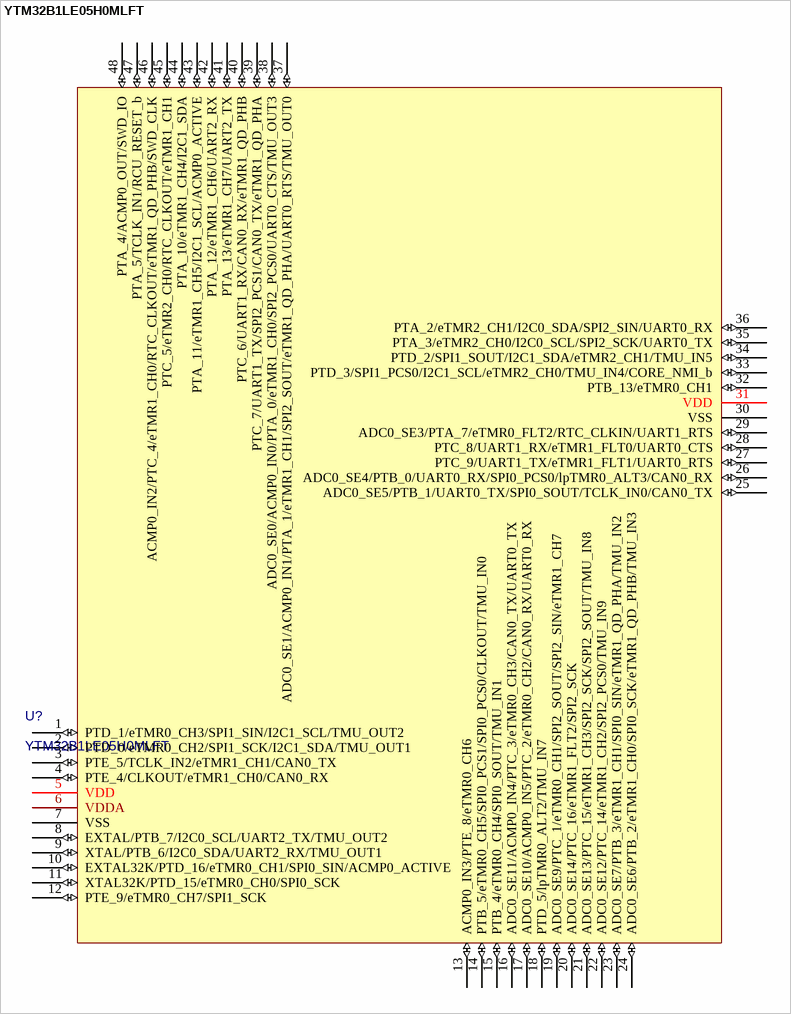
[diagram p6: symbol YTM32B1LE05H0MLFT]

## YTM32B1LE05H0MLFT
designator U?
B1L family  32-bit ARM Cortex-M0+ MCU with 128K flash and 16K SRAM, LQFP-48 package
footprint LQFP48 7X7_L
footprint LQFP48 7X7_M
footprint LQFP48 7X7_N
pins: 1 PTD_1/eTMR0_CH3/SPI1_SIN/I2C1_SCL/TMU_OUT2 (io), 2 PTD_0/eTMR0_CH2/SPI1_SCK/I2C1_SDA/TMU_OUT1 (io), 3 PTE_5/TCLK_IN2/eTMR1_CH1/CAN0_TX (io), 4 PTE_4/CLKOUT/eTMR1_CH0/CAN0_RX (io), 5 VDD, 6 VDDA, 7 VSS, 8 EXTAL/PTB_7/I2C0_SCL/UART2_TX/TMU_OUT2 (io), 9 XTAL/PTB_6/I2C0_SDA/UART2_RX/TMU_OUT1 (io), 10 EXTAL32K/PTD_16/eTMR0_CH1/SPI0_SIN/ACMP0_ACTIVE (io), 11 XTAL32K/PTD_15/eTMR0_CH0/SPI0_SCK (io), 12 PTE_9/eTMR0_CH7/SPI1_SCK (io), 13 ACMP0_IN3/PTE_8/eTMR0_CH6 (io), 14 PTB_5/eTMR0_CH5/SPI0_PCS1/SPI0_PCS0/CLKOUT/TMU_IN0 (io), 15 PTB_4/eTMR0_CH4/SPI0_SOUT/TMU_IN1 (io), 16 ADC0_SE11/ACMP0_IN4/PTC_3/eTMR0_CH3/CAN0_TX/UART0_TX (io), 17 ADC0_SE10/ACMP0_IN5/PTC_2/eTMR0_CH2/CAN0_RX/UART0_RX (io), 18 PTD_5/lpTMR0_ALT2/TMU_IN7 (io), 19 ADC0_SE9/PTC_1/eTMR0_CH1/SPI2_SOUT/SPI2_SIN/eTMR1_CH7 (io), 20 ADC0_SE14/PTC_16/eTMR1_FLT2/SPI2_SCK (io), 21 ADC0_SE13/PTC_15/eTMR1_CH3/SPI2_SCK/SPI2_SOUT/TMU_IN8 (io), 22 ADC0_SE12/PTC_14/eTMR1_CH2/SPI2_PCS0/TMU_IN9 (io), 23 ADC0_SE7/PTB_3/eTMR1_CH1/SPI0_SIN/eTMR1_QD_PHA/TMU_IN2 (io), 24 ADC0_SE6/PTB_2/eTMR1_CH0/SPI0_SCK/eTMR1_QD_PHB/TMU_IN3 (io), 25 ADC0_SE5/PTB_1/UART0_TX/SPI0_SOUT/TCLK_IN0/CAN0_TX (io), 26 ADC0_SE4/PTB_0/UART0_RX/SPI0_PCS0/lpTMR0_ALT3/CAN0_RX (io), 27 PTC_9/UART1_TX/eTMR1_FLT1/UART0_RTS (io), 28 PTC_8/UART1_RX/eTMR1_FLT0/UART0_CTS (io), 29 ADC0_SE3/PTA_7/eTMR0_FLT2/RTC_CLKIN/UART1_RTS (io), 30 VSS, 31 VDD, 32 PTB_13/eTMR0_CH1 (io), 33 PTD_3/SPI1_PCS0/I2C1_SCL/eTMR2_CH0/TMU_IN4/CORE_NMI_b (io), 34 PTD_2/SPI1_SOUT/I2C1_SDA/eTMR2_CH1/TMU_IN5 (io), 35 PTA_3/eTMR2_CH0/I2C0_SCL/SPI2_SCK/UART0_TX (io), 36 PTA_2/eTMR2_CH1/I2C0_SDA/SPI2_SIN/UART0_RX (io), 37 ADC0_SE1/ACMP0_IN1/PTA_1/eTMR1_CH1/SPI2_SOUT/eTMR1_QD_PHA/UART0_RTS/TMU_OUT0 (io), 38 ADC0_SE0/ACMP0_IN0/PTA_0/eTMR1_CH0/SPI2_PCS0/UART0_CTS/TMU_OUT3 (io), 39 PTC_7/UART1_TX/SPI2_PCS1/CAN0_TX/eTMR1_QD_PHA (io), 40 PTC_6/UART1_RX/CAN0_RX/eTMR1_QD_PHB (io), 41 PTA_13/eTMR1_CH7/UART2_TX (io), 42 PTA_12/eTMR1_CH6/UART2_RX (io), 43 PTA_11/eTMR1_CH5/I2C1_SCL/ACMP0_ACTIVE (io), 44 PTA_10/eTMR1_CH4/I2C1_SDA (io), 45 PTC_5/eTMR2_CH0/RTC_CLKOUT/eTMR1_CH1 (io), 46 ACMP0_IN2/PTC_4/eTMR1_CH0/RTC_CLKOUT/eTMR1_QD_PHB/SWD_CLK (io), 47 PTA_5/TCLK_IN1/RCU_RESET_b (io), 48 PTA_4/ACMP0_OUT/SWD_IO (io)

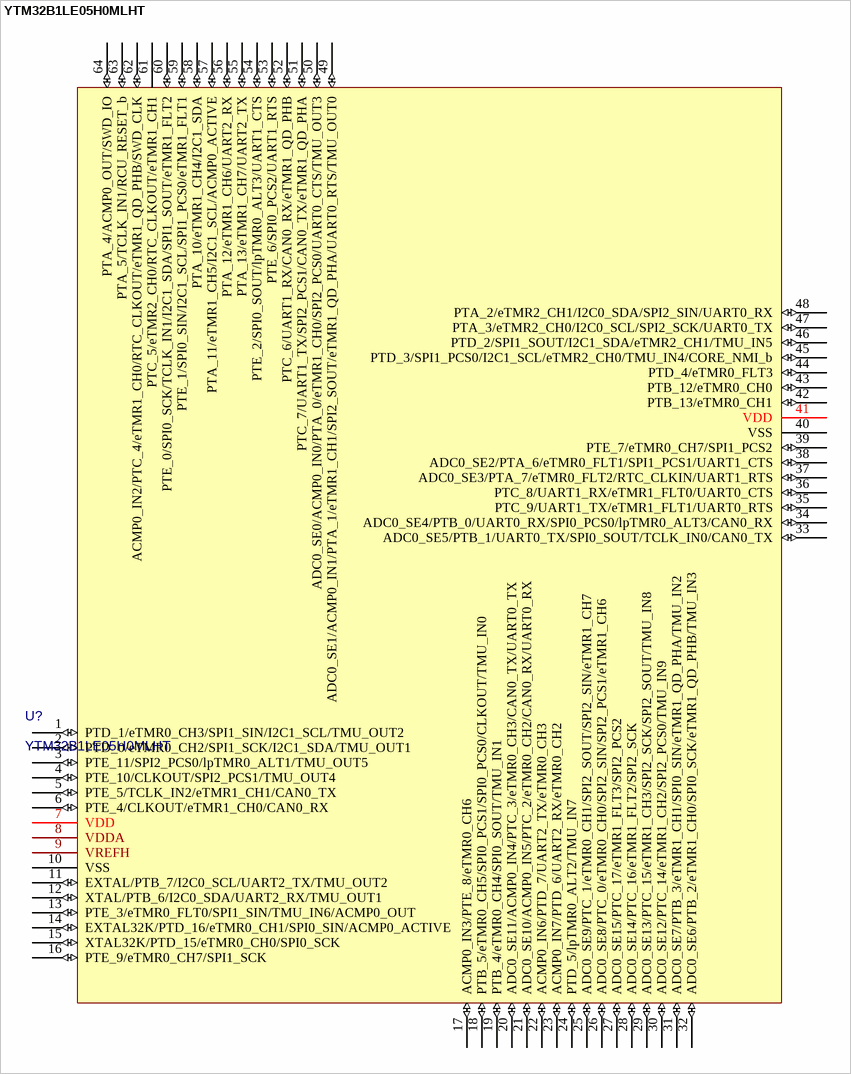
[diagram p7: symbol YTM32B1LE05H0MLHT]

## YTM32B1LE05H0MLHT
designator U?
B1L family  32-bit ARM Cortex-M0+ MCU with 128K flash and 16K SRAM, LQFP-64 package
footprint LQFP64 10x10_L
footprint LQFP64 10x10_M
footprint LQFP64 10x10_N
pins: 1 PTD_1/eTMR0_CH3/SPI1_SIN/I2C1_SCL/TMU_OUT2 (io), 2 PTD_0/eTMR0_CH2/SPI1_SCK/I2C1_SDA/TMU_OUT1 (io), 3 PTE_11/SPI2_PCS0/lpTMR0_ALT1/TMU_OUT5 (io), 4 PTE_10/CLKOUT/SPI2_PCS1/TMU_OUT4 (io), 5 PTE_5/TCLK_IN2/eTMR1_CH1/CAN0_TX (io), 6 PTE_4/CLKOUT/eTMR1_CH0/CAN0_RX (io), 7 VDD, 8 VDDA, 9 VREFH, 10 VSS, 11 EXTAL/PTB_7/I2C0_SCL/UART2_TX/TMU_OUT2 (io), 12 XTAL/PTB_6/I2C0_SDA/UART2_RX/TMU_OUT1 (io), 13 PTE_3/eTMR0_FLT0/SPI1_SIN/TMU_IN6/ACMP0_OUT (io), 14 EXTAL32K/PTD_16/eTMR0_CH1/SPI0_SIN/ACMP0_ACTIVE (io), 15 XTAL32K/PTD_15/eTMR0_CH0/SPI0_SCK (io), 16 PTE_9/eTMR0_CH7/SPI1_SCK (io), 17 ACMP0_IN3/PTE_8/eTMR0_CH6 (io), 18 PTB_5/eTMR0_CH5/SPI0_PCS1/SPI0_PCS0/CLKOUT/TMU_IN0 (io), 19 PTB_4/eTMR0_CH4/SPI0_SOUT/TMU_IN1 (io), 20 ADC0_SE11/ACMP0_IN4/PTC_3/eTMR0_CH3/CAN0_TX/UART0_TX (io), 21 ADC0_SE10/ACMP0_IN5/PTC_2/eTMR0_CH2/CAN0_RX/UART0_RX (io), 22 ACMP0_IN6/PTD_7/UART2_TX/eTMR0_CH3 (io), 23 ACMP0_IN7/PTD_6/UART2_RX/eTMR0_CH2 (io), 24 PTD_5/lpTMR0_ALT2/TMU_IN7 (io), 25 ADC0_SE9/PTC_1/eTMR0_CH1/SPI2_SOUT/SPI2_SIN/eTMR1_CH7 (io), 26 ADC0_SE8/PTC_0/eTMR0_CH0/SPI2_SIN/SPI2_PCS1/eTMR1_CH6 (io), 27 ADC0_SE15/PTC_17/eTMR1_FLT3/SPI2_PCS2 (io), 28 ADC0_SE14/PTC_16/eTMR1_FLT2/SPI2_SCK (io), 29 ADC0_SE13/PTC_15/eTMR1_CH3/SPI2_SCK/SPI2_SOUT/TMU_IN8 (io), 30 ADC0_SE12/PTC_14/eTMR1_CH2/SPI2_PCS0/TMU_IN9 (io), 31 ADC0_SE7/PTB_3/eTMR1_CH1/SPI0_SIN/eTMR1_QD_PHA/TMU_IN2 (io), 32 ADC0_SE6/PTB_2/eTMR1_CH0/SPI0_SCK/eTMR1_QD_PHB/TMU_IN3 (io), 33 ADC0_SE5/PTB_1/UART0_TX/SPI0_SOUT/TCLK_IN0/CAN0_TX (io), 34 ADC0_SE4/PTB_0/UART0_RX/SPI0_PCS0/lpTMR0_ALT3/CAN0_RX (io), 35 PTC_9/UART1_TX/eTMR1_FLT1/UART0_RTS (io), 36 PTC_8/UART1_RX/eTMR1_FLT0/UART0_CTS (io), 37 ADC0_SE3/PTA_7/eTMR0_FLT2/RTC_CLKIN/UART1_RTS (io), 38 ADC0_SE2/PTA_6/eTMR0_FLT1/SPI1_PCS1/UART1_CTS (io), 39 PTE_7/eTMR0_CH7/SPI1_PCS2 (io), 40 VSS, 41 VDD, 42 PTB_13/eTMR0_CH1 (io), 43 PTB_12/eTMR0_CH0 (io), 44 PTD_4/eTMR0_FLT3 (io), 45 PTD_3/SPI1_PCS0/I2C1_SCL/eTMR2_CH0/TMU_IN4/CORE_NMI_b (io), 46 PTD_2/SPI1_SOUT/I2C1_SDA/eTMR2_CH1/TMU_IN5 (io), 47 PTA_3/eTMR2_CH0/I2C0_SCL/SPI2_SCK/UART0_TX (io), 48 PTA_2/eTMR2_CH1/I2C0_SDA/SPI2_SIN/UART0_RX (io), 49 ADC0_SE1/ACMP0_IN1/PTA_1/eTMR1_CH1/SPI2_SOUT/eTMR1_QD_PHA/UART0_RTS/TMU_OUT0 (io), 50 ADC0_SE0/ACMP0_IN0/PTA_0/eTMR1_CH0/SPI2_PCS0/UART0_CTS/TMU_OUT3 (io), 51 PTC_7/UART1_TX/SPI2_PCS1/CAN0_TX/eTMR1_QD_PHA (io), 52 PTC_6/UART1_RX/CAN0_RX/eTMR1_QD_PHB (io), 53 PTE_6/SPI0_PCS2/UART1_RTS (io), 54 PTE_2/SPI0_SOUT/lpTMR0_ALT3/UART1_CTS (io), 55 PTA_13/eTMR1_CH7/UART2_TX (io), 56 PTA_12/eTMR1_CH6/UART2_RX (io), 57 PTA_11/eTMR1_CH5/I2C1_SCL/ACMP0_ACTIVE (io), 58 PTA_10/eTMR1_CH4/I2C1_SDA (io), 59 PTE_1/SPI0_SIN/I2C1_SCL/SPI1_PCS0/eTMR1_FLT1 (io), 60 PTE_0/SPI0_SCK/TCLK_IN1/I2C1_SDA/SPI1_SOUT/eTMR1_FLT2 (io), 61 PTC_5/eTMR2_CH0/RTC_CLKOUT/eTMR1_CH1, 62 ACMP0_IN2/PTC_4/eTMR1_CH0/RTC_CLKOUT/eTMR1_QD_PHB/SWD_CLK (io), 63 PTA_5/TCLK_IN1/RCU_RESET_b (io), 64 PTA_4/ACMP0_OUT/SWD_IO (io)

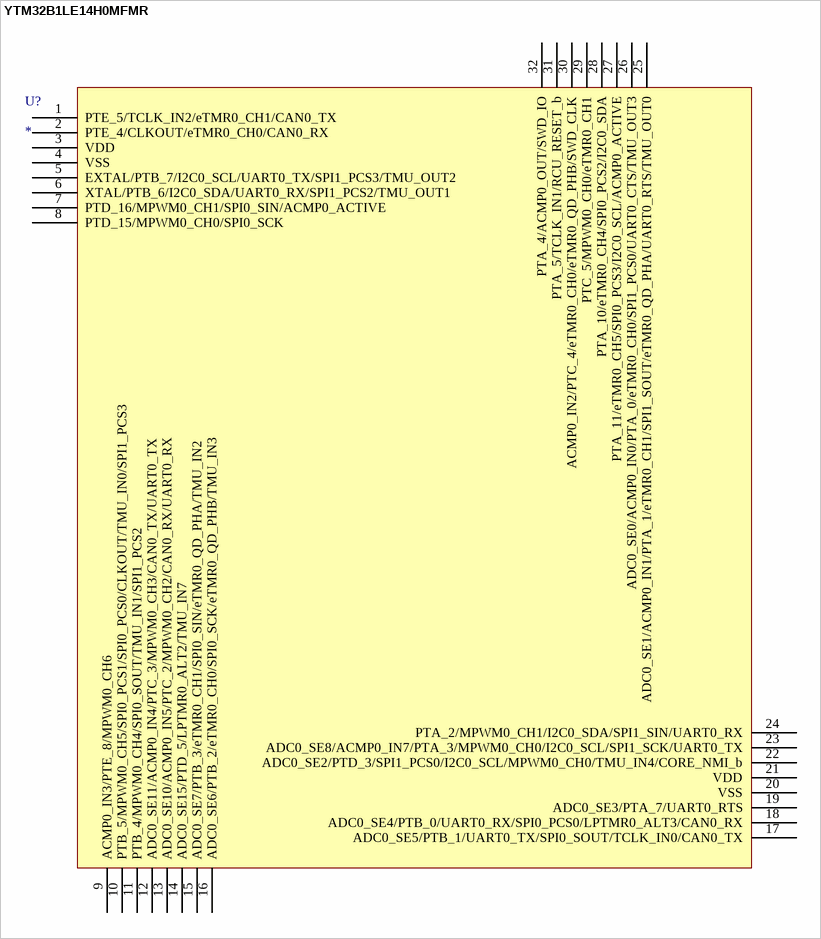
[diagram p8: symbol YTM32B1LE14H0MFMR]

## YTM32B1LE14H0MFMR
designator U?
B1L family  32-bit ARM Cortex-M0+ MCU with 64K flash and 8K SRAM, QFN-32 package
footprint QFN32 (Footprint not found)
pins: 1 PTE_5/TCLK_IN2/eTMR0_CH1/CAN0_TX, 2 PTE_4/CLKOUT/eTMR0_CH0/CAN0_RX, 3 VDD, 4 VSS, 5 EXTAL/PTB_7/I2C0_SCL/UART0_TX/SPI1_PCS3/TMU_OUT2, 6 XTAL/PTB_6/I2C0_SDA/UART0_RX/SPI1_PCS2/TMU_OUT1, 7 PTD_16/MPWM0_CH1/SPI0_SIN/ACMP0_ACTIVE, 8 PTD_15/MPWM0_CH0/SPI0_SCK, 9 ACMP0_IN3/PTE_8/MPWM0_CH6, 10 PTB_5/MPWM0_CH5/SPI0_PCS1/SPI0_PCS0/CLKOUT/TMU_IN0/SPI1_PCS3, 11 PTB_4/MPWM0_CH4/SPI0_SOUT/TMU_IN1/SPI1_PCS2, 12 ADC0_SE11/ACMP0_IN4/PTC_3/MPWM0_CH3/CAN0_TX/UART0_TX, 13 ADC0_SE10/ACMP0_IN5/PTC_2/MPWM0_CH2/CAN0_RX/UART0_RX, 14 ADC0_SE15/PTD_5/LPTMR0_ALT2/TMU_IN7, 15 ADC0_SE7/PTB_3/eTMR0_CH1/SPI0_SIN/eTMR0_QD_PHA/TMU_IN2, 16 ADC0_SE6/PTB_2/eTMR0_CH0/SPI0_SCK/eTMR0_QD_PHB/TMU_IN3, 17 ADC0_SE5/PTB_1/UART0_TX/SPI0_SOUT/TCLK_IN0/CAN0_TX, 18 ADC0_SE4/PTB_0/UART0_RX/SPI0_PCS0/LPTMR0_ALT3/CAN0_RX, 19 ADC0_SE3/PTA_7/UART0_RTS, 20 VSS, 21 VDD, 22 ADC0_SE2/PTD_3/SPI1_PCS0/I2C0_SCL/MPWM0_CH0/TMU_IN4/CORE_NMI_b, 23 ADC0_SE8/ACMP0_IN7/PTA_3/MPWM0_CH0/I2C0_SCL/SPI1_SCK/UART0_TX, 24 PTA_2/MPWM0_CH1/I2C0_SDA/SPI1_SIN/UART0_RX, 25 ADC0_SE1/ACMP0_IN1/PTA_1/eTMR0_CH1/SPI1_SOUT/eTMR0_QD_PHA/UART0_RTS/TMU_OUT0, 26 ADC0_SE0/ACMP0_IN0/PTA_0/eTMR0_CH0/SPI1_PCS0/UART0_CTS/TMU_OUT3, 27 PTA_11/eTMR0_CH5/SPI0_PCS3/I2C0_SCL/ACMP0_ACTIVE, 28 PTA_10/eTMR0_CH4/SPI0_PCS2/I2C0_SDA, 29 PTC_5/MPWM0_CH0/eTMR0_CH1, 30 ACMP0_IN2/PTC_4/eTMR0_CH0/eTMR0_QD_PHB/SWD_CLK, 31 PTA_5/TCLK_IN1/RCU_RESET_b, 32 PTA_4/ACMP0_OUT/SWD_IO

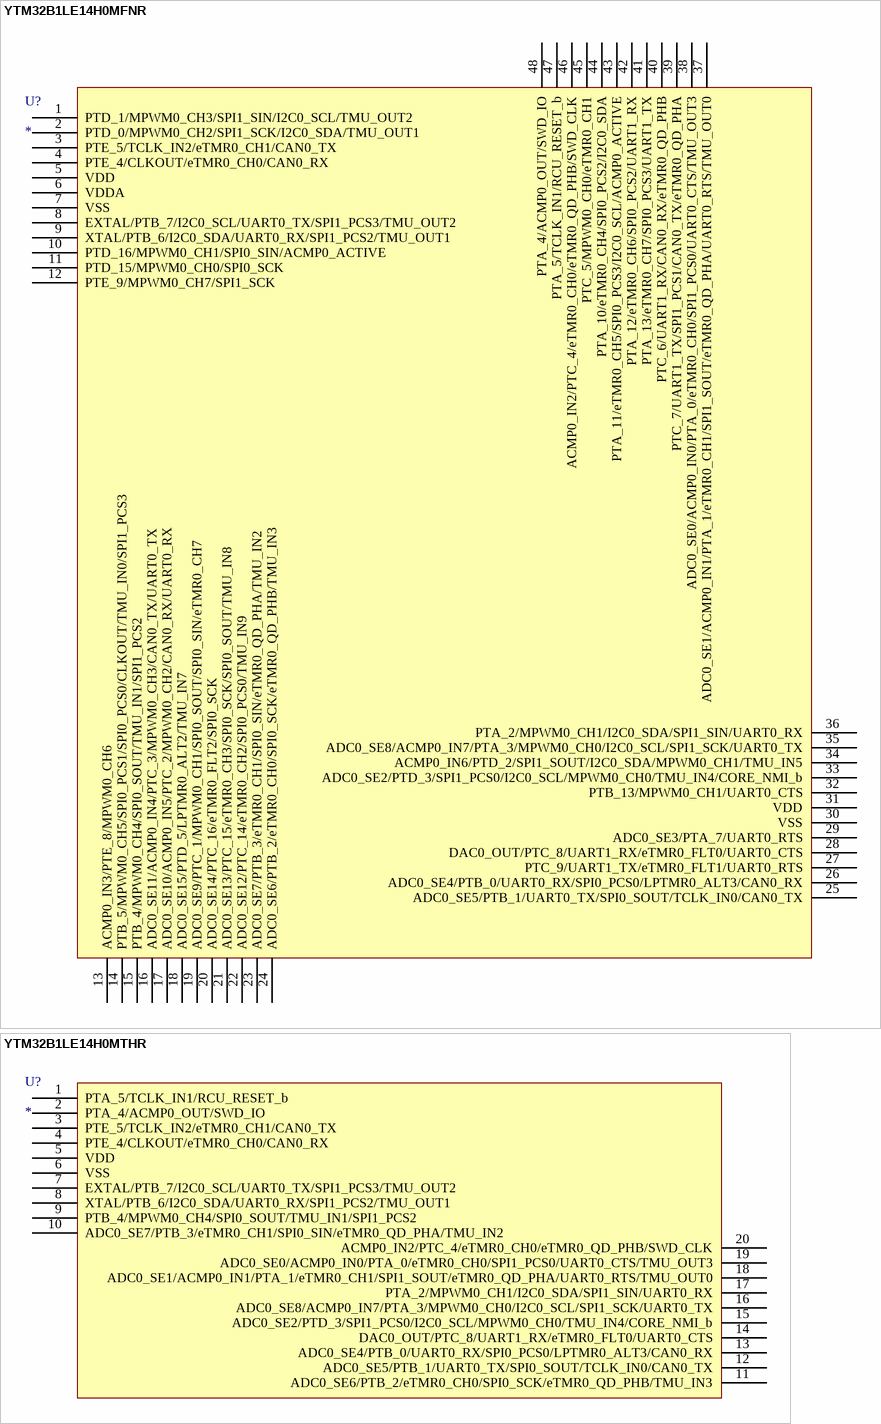
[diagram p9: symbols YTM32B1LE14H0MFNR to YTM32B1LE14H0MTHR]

## YTM32B1LE14H0MFNR
designator U?
B1L family  32-bit ARM Cortex-M0+ MCU with 64K flash and 8K SRAM, QFN-48 package
footprint QFN48 (Footprint not found)
pins: 1 PTD_1/MPWM0_CH3/SPI1_SIN/I2C0_SCL/TMU_OUT2, 2 PTD_0/MPWM0_CH2/SPI1_SCK/I2C0_SDA/TMU_OUT1, 3 PTE_5/TCLK_IN2/eTMR0_CH1/CAN0_TX, 4 PTE_4/CLKOUT/eTMR0_CH0/CAN0_RX, 5 VDD, 6 VDDA, 7 VSS, 8 EXTAL/PTB_7/I2C0_SCL/UART0_TX/SPI1_PCS3/TMU_OUT2, 9 XTAL/PTB_6/I2C0_SDA/UART0_RX/SPI1_PCS2/TMU_OUT1, 10 PTD_16/MPWM0_CH1/SPI0_SIN/ACMP0_ACTIVE, 11 PTD_15/MPWM0_CH0/SPI0_SCK, 12 PTE_9/MPWM0_CH7/SPI1_SCK, 13 ACMP0_IN3/PTE_8/MPWM0_CH6, 14 PTB_5/MPWM0_CH5/SPI0_PCS1/SPI0_PCS0/CLKOUT/TMU_IN0/SPI1_PCS3, 15 PTB_4/MPWM0_CH4/SPI0_SOUT/TMU_IN1/SPI1_PCS2, 16 ADC0_SE11/ACMP0_IN4/PTC_3/MPWM0_CH3/CAN0_TX/UART0_TX, 17 ADC0_SE10/ACMP0_IN5/PTC_2/MPWM0_CH2/CAN0_RX/UART0_RX, 18 ADC0_SE15/PTD_5/LPTMR0_ALT2/TMU_IN7, 19 ADC0_SE9/PTC_1/MPWM0_CH1/SPI0_SOUT/SPI0_SIN/eTMR0_CH7, 20 ADC0_SE14/PTC_16/eTMR0_FLT2/SPI0_SCK, 21 ADC0_SE13/PTC_15/eTMR0_CH3/SPI0_SCK/SPI0_SOUT/TMU_IN8, 22 ADC0_SE12/PTC_14/eTMR0_CH2/SPI0_PCS0/TMU_IN9, 23 ADC0_SE7/PTB_3/eTMR0_CH1/SPI0_SIN/eTMR0_QD_PHA/TMU_IN2, 24 ADC0_SE6/PTB_2/eTMR0_CH0/SPI0_SCK/eTMR0_QD_PHB/TMU_IN3, 25 ADC0_SE5/PTB_1/UART0_TX/SPI0_SOUT/TCLK_IN0/CAN0_TX, 26 ADC0_SE4/PTB_0/UART0_RX/SPI0_PCS0/LPTMR0_ALT3/CAN0_RX, 27 PTC_9/UART1_TX/eTMR0_FLT1/UART0_RTS, 28 DAC0_OUT/PTC_8/UART1_RX/eTMR0_FLT0/UART0_CTS, 29 ADC0_SE3/PTA_7/UART0_RTS, 30 VSS, 31 VDD, 32 PTB_13/MPWM0_CH1/UART0_CTS, 33 ADC0_SE2/PTD_3/SPI1_PCS0/I2C0_SCL/MPWM0_CH0/TMU_IN4/CORE_NMI_b, 34 ACMP0_IN6/PTD_2/SPI1_SOUT/I2C0_SDA/MPWM0_CH1/TMU_IN5, 35 ADC0_SE8/ACMP0_IN7/PTA_3/MPWM0_CH0/I2C0_SCL/SPI1_SCK/UART0_TX, 36 PTA_2/MPWM0_CH1/I2C0_SDA/SPI1_SIN/UART0_RX, 37 ADC0_SE1/ACMP0_IN1/PTA_1/eTMR0_CH1/SPI1_SOUT/eTMR0_QD_PHA/UART0_RTS/TMU_OUT0, 38 ADC0_SE0/ACMP0_IN0/PTA_0/eTMR0_CH0/SPI1_PCS0/UART0_CTS/TMU_OUT3, 39 PTC_7/UART1_TX/SPI1_PCS1/CAN0_TX/eTMR0_QD_PHA, 40 PTC_6/UART1_RX/CAN0_RX/eTMR0_QD_PHB, 41 PTA_13/eTMR0_CH7/SPI0_PCS3/UART1_TX, 42 PTA_12/eTMR0_CH6/SPI0_PCS2/UART1_RX, 43 PTA_11/eTMR0_CH5/SPI0_PCS3/I2C0_SCL/ACMP0_ACTIVE, 44 PTA_10/eTMR0_CH4/SPI0_PCS2/I2C0_SDA, 45 PTC_5/MPWM0_CH0/eTMR0_CH1, 46 ACMP0_IN2/PTC_4/eTMR0_CH0/eTMR0_QD_PHB/SWD_CLK, 47 PTA_5/TCLK_IN1/RCU_RESET_b, 48 PTA_4/ACMP0_OUT/SWD_IO

## YTM32B1LE14H0MTHR
designator U?
B1L family  32-bit ARM Cortex-M0+ MCU with 64K flash and 8K SRAM, TSSOP-20 package
footprint TSSOP20 (Footprint not found)
pins: 1 PTA_5/TCLK_IN1/RCU_RESET_b, 2 PTA_4/ACMP0_OUT/SWD_IO, 3 PTE_5/TCLK_IN2/eTMR0_CH1/CAN0_TX, 4 PTE_4/CLKOUT/eTMR0_CH0/CAN0_RX, 5 VDD, 6 VSS, 7 EXTAL/PTB_7/I2C0_SCL/UART0_TX/SPI1_PCS3/TMU_OUT2, 8 XTAL/PTB_6/I2C0_SDA/UART0_RX/SPI1_PCS2/TMU_OUT1, 9 PTB_4/MPWM0_CH4/SPI0_SOUT/TMU_IN1/SPI1_PCS2, 10 ADC0_SE7/PTB_3/eTMR0_CH1/SPI0_SIN/eTMR0_QD_PHA/TMU_IN2, 11 ADC0_SE6/PTB_2/eTMR0_CH0/SPI0_SCK/eTMR0_QD_PHB/TMU_IN3, 12 ADC0_SE5/PTB_1/UART0_TX/SPI0_SOUT/TCLK_IN0/CAN0_TX, 13 ADC0_SE4/PTB_0/UART0_RX/SPI0_PCS0/LPTMR0_ALT3/CAN0_RX, 14 DAC0_OUT/PTC_8/UART1_RX/eTMR0_FLT0/UART0_CTS, 15 ADC0_SE2/PTD_3/SPI1_PCS0/I2C0_SCL/MPWM0_CH0/TMU_IN4/CORE_NMI_b, 16 ADC0_SE8/ACMP0_IN7/PTA_3/MPWM0_CH0/I2C0_SCL/SPI1_SCK/UART0_TX, 17 PTA_2/MPWM0_CH1/I2C0_SDA/SPI1_SIN/UART0_RX, 18 ADC0_SE1/ACMP0_IN1/PTA_1/eTMR0_CH1/SPI1_SOUT/eTMR0_QD_PHA/UART0_RTS/TMU_OUT0, 19 ADC0_SE0/ACMP0_IN0/PTA_0/eTMR0_CH0/SPI1_PCS0/UART0_CTS/TMU_OUT3, 20 ACMP0_IN2/PTC_4/eTMR0_CH0/eTMR0_QD_PHB/SWD_CLK

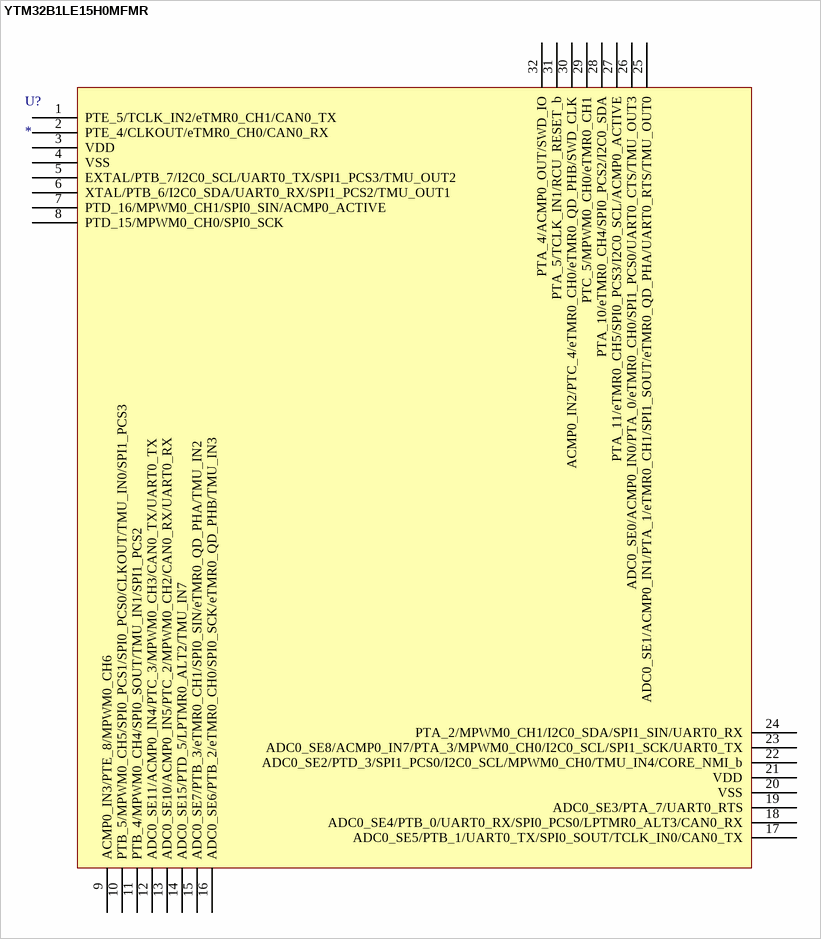
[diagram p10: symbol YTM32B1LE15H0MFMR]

## YTM32B1LE15H0MFMR
designator U?
B1L family  32-bit ARM Cortex-M0+ MCU with 128K flash and 16K SRAM, QFN-32 package
footprint QFN32 (Footprint not found)
pins: 1 PTE_5/TCLK_IN2/eTMR0_CH1/CAN0_TX, 2 PTE_4/CLKOUT/eTMR0_CH0/CAN0_RX, 3 VDD, 4 VSS, 5 EXTAL/PTB_7/I2C0_SCL/UART0_TX/SPI1_PCS3/TMU_OUT2, 6 XTAL/PTB_6/I2C0_SDA/UART0_RX/SPI1_PCS2/TMU_OUT1, 7 PTD_16/MPWM0_CH1/SPI0_SIN/ACMP0_ACTIVE, 8 PTD_15/MPWM0_CH0/SPI0_SCK, 9 ACMP0_IN3/PTE_8/MPWM0_CH6, 10 PTB_5/MPWM0_CH5/SPI0_PCS1/SPI0_PCS0/CLKOUT/TMU_IN0/SPI1_PCS3, 11 PTB_4/MPWM0_CH4/SPI0_SOUT/TMU_IN1/SPI1_PCS2, 12 ADC0_SE11/ACMP0_IN4/PTC_3/MPWM0_CH3/CAN0_TX/UART0_TX, 13 ADC0_SE10/ACMP0_IN5/PTC_2/MPWM0_CH2/CAN0_RX/UART0_RX, 14 ADC0_SE15/PTD_5/LPTMR0_ALT2/TMU_IN7, 15 ADC0_SE7/PTB_3/eTMR0_CH1/SPI0_SIN/eTMR0_QD_PHA/TMU_IN2, 16 ADC0_SE6/PTB_2/eTMR0_CH0/SPI0_SCK/eTMR0_QD_PHB/TMU_IN3, 17 ADC0_SE5/PTB_1/UART0_TX/SPI0_SOUT/TCLK_IN0/CAN0_TX, 18 ADC0_SE4/PTB_0/UART0_RX/SPI0_PCS0/LPTMR0_ALT3/CAN0_RX, 19 ADC0_SE3/PTA_7/UART0_RTS, 20 VSS, 21 VDD, 22 ADC0_SE2/PTD_3/SPI1_PCS0/I2C0_SCL/MPWM0_CH0/TMU_IN4/CORE_NMI_b, 23 ADC0_SE8/ACMP0_IN7/PTA_3/MPWM0_CH0/I2C0_SCL/SPI1_SCK/UART0_TX, 24 PTA_2/MPWM0_CH1/I2C0_SDA/SPI1_SIN/UART0_RX, 25 ADC0_SE1/ACMP0_IN1/PTA_1/eTMR0_CH1/SPI1_SOUT/eTMR0_QD_PHA/UART0_RTS/TMU_OUT0, 26 ADC0_SE0/ACMP0_IN0/PTA_0/eTMR0_CH0/SPI1_PCS0/UART0_CTS/TMU_OUT3, 27 PTA_11/eTMR0_CH5/SPI0_PCS3/I2C0_SCL/ACMP0_ACTIVE, 28 PTA_10/eTMR0_CH4/SPI0_PCS2/I2C0_SDA, 29 PTC_5/MPWM0_CH0/eTMR0_CH1, 30 ACMP0_IN2/PTC_4/eTMR0_CH0/eTMR0_QD_PHB/SWD_CLK, 31 PTA_5/TCLK_IN1/RCU_RESET_b, 32 PTA_4/ACMP0_OUT/SWD_IO

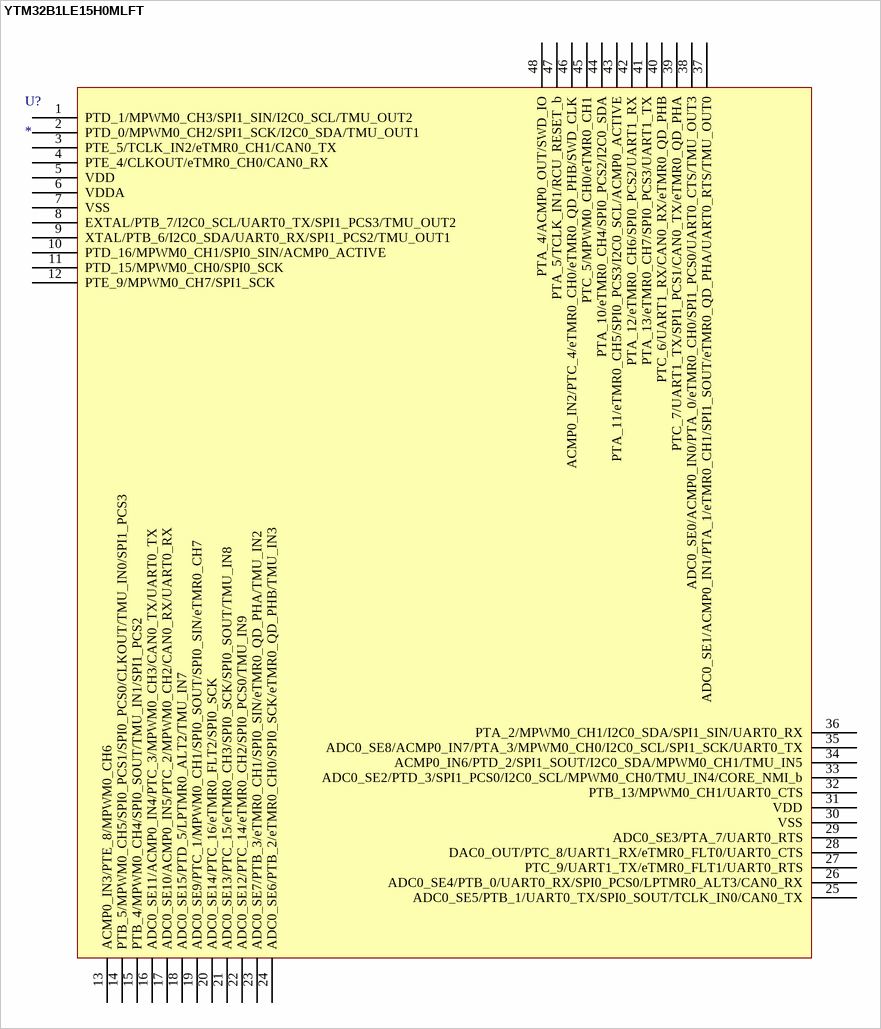
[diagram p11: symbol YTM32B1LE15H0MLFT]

## YTM32B1LE15H0MLFT
designator U?
B1L family  32-bit ARM Cortex-M0+ MCU with 128K flash and 16K SRAM, LQFP-48 package
footprint LQFP48 7X7_M (Footprint not found)
pins: 1 PTD_1/MPWM0_CH3/SPI1_SIN/I2C0_SCL/TMU_OUT2, 2 PTD_0/MPWM0_CH2/SPI1_SCK/I2C0_SDA/TMU_OUT1, 3 PTE_5/TCLK_IN2/eTMR0_CH1/CAN0_TX, 4 PTE_4/CLKOUT/eTMR0_CH0/CAN0_RX, 5 VDD, 6 VDDA, 7 VSS, 8 EXTAL/PTB_7/I2C0_SCL/UART0_TX/SPI1_PCS3/TMU_OUT2, 9 XTAL/PTB_6/I2C0_SDA/UART0_RX/SPI1_PCS2/TMU_OUT1, 10 PTD_16/MPWM0_CH1/SPI0_SIN/ACMP0_ACTIVE, 11 PTD_15/MPWM0_CH0/SPI0_SCK, 12 PTE_9/MPWM0_CH7/SPI1_SCK, 13 ACMP0_IN3/PTE_8/MPWM0_CH6, 14 PTB_5/MPWM0_CH5/SPI0_PCS1/SPI0_PCS0/CLKOUT/TMU_IN0/SPI1_PCS3, 15 PTB_4/MPWM0_CH4/SPI0_SOUT/TMU_IN1/SPI1_PCS2, 16 ADC0_SE11/ACMP0_IN4/PTC_3/MPWM0_CH3/CAN0_TX/UART0_TX, 17 ADC0_SE10/ACMP0_IN5/PTC_2/MPWM0_CH2/CAN0_RX/UART0_RX, 18 ADC0_SE15/PTD_5/LPTMR0_ALT2/TMU_IN7, 19 ADC0_SE9/PTC_1/MPWM0_CH1/SPI0_SOUT/SPI0_SIN/eTMR0_CH7, 20 ADC0_SE14/PTC_16/eTMR0_FLT2/SPI0_SCK, 21 ADC0_SE13/PTC_15/eTMR0_CH3/SPI0_SCK/SPI0_SOUT/TMU_IN8, 22 ADC0_SE12/PTC_14/eTMR0_CH2/SPI0_PCS0/TMU_IN9, 23 ADC0_SE7/PTB_3/eTMR0_CH1/SPI0_SIN/eTMR0_QD_PHA/TMU_IN2, 24 ADC0_SE6/PTB_2/eTMR0_CH0/SPI0_SCK/eTMR0_QD_PHB/TMU_IN3, 25 ADC0_SE5/PTB_1/UART0_TX/SPI0_SOUT/TCLK_IN0/CAN0_TX, 26 ADC0_SE4/PTB_0/UART0_RX/SPI0_PCS0/LPTMR0_ALT3/CAN0_RX, 27 PTC_9/UART1_TX/eTMR0_FLT1/UART0_RTS, 28 DAC0_OUT/PTC_8/UART1_RX/eTMR0_FLT0/UART0_CTS, 29 ADC0_SE3/PTA_7/UART0_RTS, 30 VSS, 31 VDD, 32 PTB_13/MPWM0_CH1/UART0_CTS, 33 ADC0_SE2/PTD_3/SPI1_PCS0/I2C0_SCL/MPWM0_CH0/TMU_IN4/CORE_NMI_b, 34 ACMP0_IN6/PTD_2/SPI1_SOUT/I2C0_SDA/MPWM0_CH1/TMU_IN5, 35 ADC0_SE8/ACMP0_IN7/PTA_3/MPWM0_CH0/I2C0_SCL/SPI1_SCK/UART0_TX, 36 PTA_2/MPWM0_CH1/I2C0_SDA/SPI1_SIN/UART0_RX, 37 ADC0_SE1/ACMP0_IN1/PTA_1/eTMR0_CH1/SPI1_SOUT/eTMR0_QD_PHA/UART0_RTS/TMU_OUT0, 38 ADC0_SE0/ACMP0_IN0/PTA_0/eTMR0_CH0/SPI1_PCS0/UART0_CTS/TMU_OUT3, 39 PTC_7/UART1_TX/SPI1_PCS1/CAN0_TX/eTMR0_QD_PHA, 40 PTC_6/UART1_RX/CAN0_RX/eTMR0_QD_PHB, 41 PTA_13/eTMR0_CH7/SPI0_PCS3/UART1_TX, 42 PTA_12/eTMR0_CH6/SPI0_PCS2/UART1_RX, 43 PTA_11/eTMR0_CH5/SPI0_PCS3/I2C0_SCL/ACMP0_ACTIVE, 44 PTA_10/eTMR0_CH4/SPI0_PCS2/I2C0_SDA, 45 PTC_5/MPWM0_CH0/eTMR0_CH1, 46 ACMP0_IN2/PTC_4/eTMR0_CH0/eTMR0_QD_PHB/SWD_CLK, 47 PTA_5/TCLK_IN1/RCU_RESET_b, 48 PTA_4/ACMP0_OUT/SWD_IO

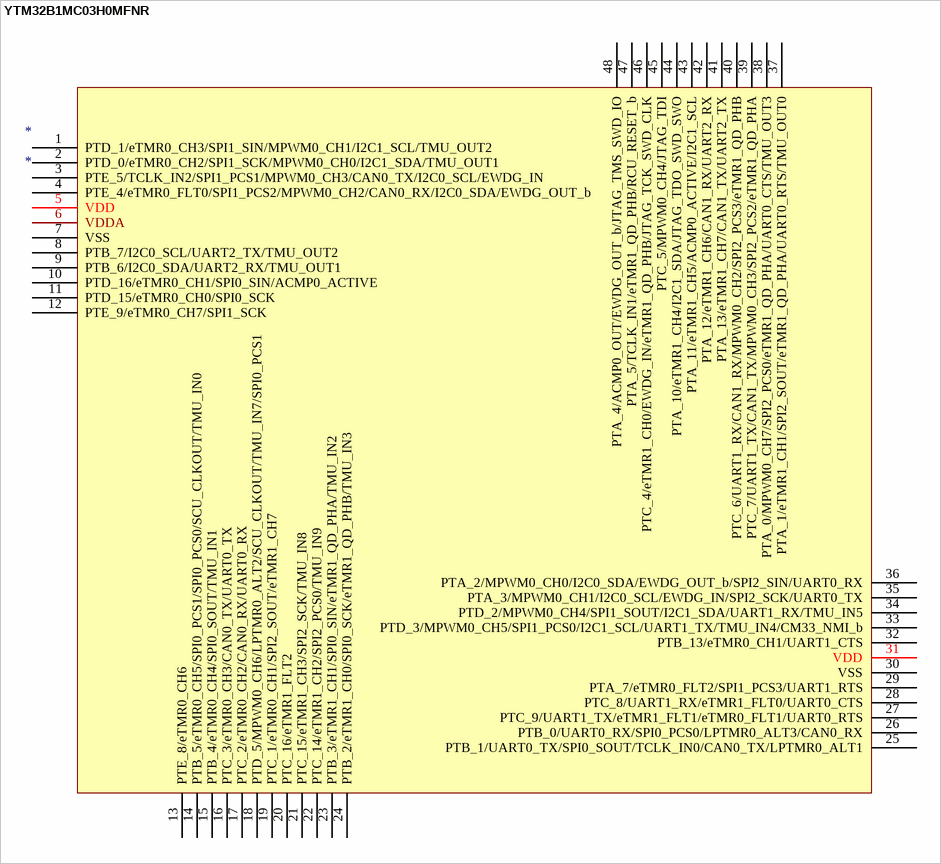
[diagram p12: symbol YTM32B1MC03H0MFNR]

## YTM32B1MC03H0MFNR
designator *
B1M family  32-bit ARM Cortex-M33 MCU with 256K pflash and 32K SRAM, QFN-48 package
footprint QFN48 (QFN, 48-Leads, Body 7.1x7.1mm, Pitch 0.5mm, Thermal Pad 5.6x5.6mm, IPC Low Density)
pins: 1 PTD_1/eTMR0_CH3/SPI1_SIN/MPWM0_CH1/I2C1_SCL/TMU_OUT2, 2 PTD_0/eTMR0_CH2/SPI1_SCK/MPWM0_CH0/I2C1_SDA/TMU_OUT1, 3 PTE_5/TCLK_IN2/SPI1_PCS1/MPWM0_CH3/CAN0_TX/I2C0_SCL/EWDG_IN, 4 PTE_4/eTMR0_FLT0/SPI1_PCS2/MPWM0_CH2/CAN0_RX/I2C0_SDA/EWDG_OUT_b, 5 VDD, 6 VDDA, 7 VSS, 8 PTB_7/I2C0_SCL/UART2_TX/TMU_OUT2, 9 PTB_6/I2C0_SDA/UART2_RX/TMU_OUT1, 10 PTD_16/eTMR0_CH1/SPI0_SIN/ACMP0_ACTIVE, 11 PTD_15/eTMR0_CH0/SPI0_SCK, 12 PTE_9/eTMR0_CH7/SPI1_SCK, 13 PTE_8/eTMR0_CH6, 14 PTB_5/eTMR0_CH5/SPI0_PCS1/SPI0_PCS0/SCU_CLKOUT/TMU_IN0, 15 PTB_4/eTMR0_CH4/SPI0_SOUT/TMU_IN1, 16 PTC_3/eTMR0_CH3/CAN0_TX/UART0_TX, 17 PTC_2/eTMR0_CH2/CAN0_RX/UART0_RX, 18 PTD_5/MPWM0_CH6/LPTMR0_ALT2/SCU_CLKOUT/TMU_IN7/SPI0_PCS1, 19 PTC_1/eTMR0_CH1/SPI2_SOUT/eTMR1_CH7, 20 PTC_16/eTMR1_FLT2, 21 PTC_15/eTMR1_CH3/SPI2_SCK/TMU_IN8, 22 PTC_14/eTMR1_CH2/SPI2_PCS0/TMU_IN9, 23 PTB_3/eTMR1_CH1/SPI0_SIN/eTMR1_QD_PHA/TMU_IN2, 24 PTB_2/eTMR1_CH0/SPI0_SCK/eTMR1_QD_PHB/TMU_IN3, 25 PTB_1/UART0_TX/SPI0_SOUT/TCLK_IN0/CAN0_TX/LPTMR0_ALT1, 26 PTB_0/UART0_RX/SPI0_PCS0/LPTMR0_ALT3/CAN0_RX, 27 PTC_9/UART1_TX/eTMR1_FLT1/eTMR0_FLT1/UART0_RTS, 28 PTC_8/UART1_RX/eTMR1_FLT0/UART0_CTS, 29 PTA_7/eTMR0_FLT2/SPI1_PCS3/UART1_RTS, 30 VSS, 31 VDD, 32 PTB_13/eTMR0_CH1/UART1_CTS, 33 PTD_3/MPWM0_CH5/SPI1_PCS0/I2C1_SCL/UART1_TX/TMU_IN4/CM33_NMI_b, 34 PTD_2/MPWM0_CH4/SPI1_SOUT/I2C1_SDA/UART1_RX/TMU_IN5, 35 PTA_3/MPWM0_CH1/I2C0_SCL/EWDG_IN/SPI2_SCK/UART0_TX, 36 PTA_2/MPWM0_CH0/I2C0_SDA/EWDG_OUT_b/SPI2_SIN/UART0_RX, 37 PTA_1/eTMR1_CH1/SPI2_SOUT/eTMR1_QD_PHA/UART0_RTS/TMU_OUT0, 38 PTA_0/MPWM0_CH7/SPI2_PCS0/eTMR1_QD_PHA/UART0_CTS/TMU_OUT3, 39 PTC_7/UART1_TX/CAN1_TX/MPWM0_CH3/SPI2_PCS2/eTMR1_QD_PHA, 40 PTC_6/UART1_RX/CAN1_RX/MPWM0_CH2/SPI2_PCS3/eTMR1_QD_PHB, 41 PTA_13/eTMR1_CH7/CAN1_TX/UART2_TX, 42 PTA_12/eTMR1_CH6/CAN1_RX/UART2_RX, 43 PTA_11/eTMR1_CH5/ACMP0_ACTIVE/I2C1_SCL, 44 PTA_10/eTMR1_CH4/I2C1_SDA/JTAG_TDO_SWD_SWO, 45 PTC_5/MPWM0_CH4/JTAG_TDI, 46 PTC_4/eTMR1_CH0/EWDG_IN/eTMR1_QD_PHB/JTAG_TCK_SWD_CLK, 47 PTA_5/TCLK_IN1/eTMR1_QD_PHB/RCU_RESET_b, 48 PTA_4/ACMP0_OUT/EWDG_OUT_b/JTAG_TMS_SWD_IO

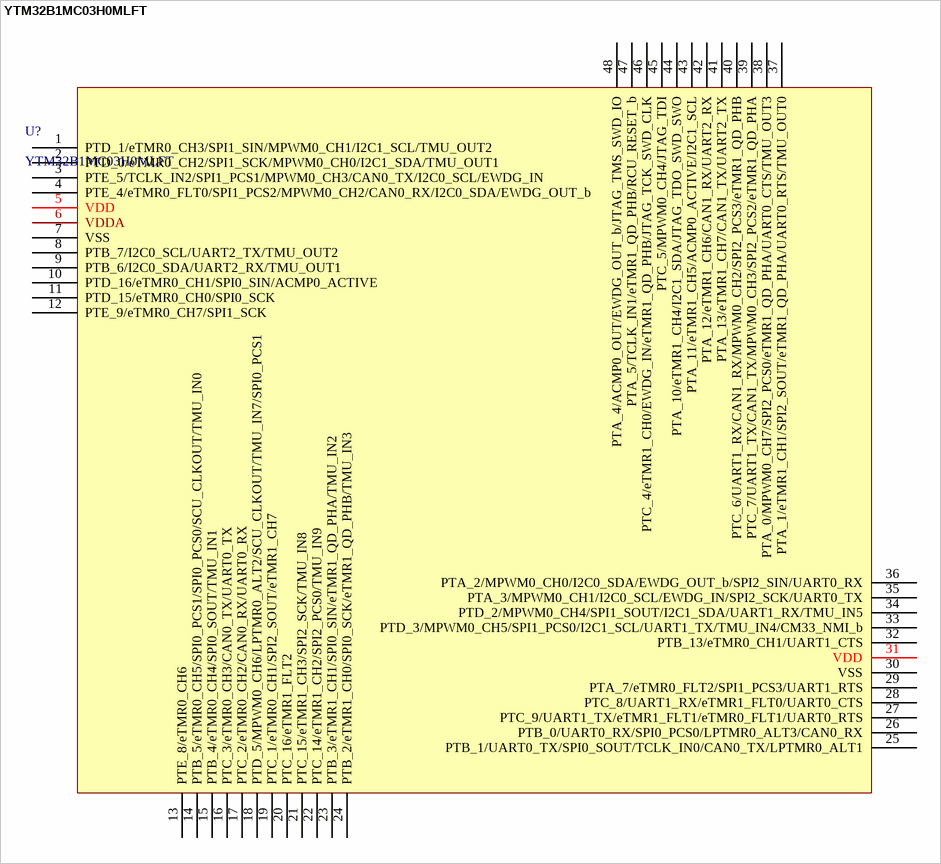
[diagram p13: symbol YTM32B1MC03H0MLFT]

## YTM32B1MC03H0MLFT
designator U?
B1M family  32-bit ARM Cortex-M33 MCU with 256K pflash and 32K SRAM, LQFP-48 package
footprint LQFP48 7X7_M
footprint LQFP48 7X7_L
footprint LQFP48 7X7_N
pins: 1 PTD_1/eTMR0_CH3/SPI1_SIN/MPWM0_CH1/I2C1_SCL/TMU_OUT2, 2 PTD_0/eTMR0_CH2/SPI1_SCK/MPWM0_CH0/I2C1_SDA/TMU_OUT1, 3 PTE_5/TCLK_IN2/SPI1_PCS1/MPWM0_CH3/CAN0_TX/I2C0_SCL/EWDG_IN, 4 PTE_4/eTMR0_FLT0/SPI1_PCS2/MPWM0_CH2/CAN0_RX/I2C0_SDA/EWDG_OUT_b, 5 VDD, 6 VDDA, 7 VSS, 8 PTB_7/I2C0_SCL/UART2_TX/TMU_OUT2, 9 PTB_6/I2C0_SDA/UART2_RX/TMU_OUT1, 10 PTD_16/eTMR0_CH1/SPI0_SIN/ACMP0_ACTIVE, 11 PTD_15/eTMR0_CH0/SPI0_SCK, 12 PTE_9/eTMR0_CH7/SPI1_SCK, 13 PTE_8/eTMR0_CH6, 14 PTB_5/eTMR0_CH5/SPI0_PCS1/SPI0_PCS0/SCU_CLKOUT/TMU_IN0, 15 PTB_4/eTMR0_CH4/SPI0_SOUT/TMU_IN1, 16 PTC_3/eTMR0_CH3/CAN0_TX/UART0_TX, 17 PTC_2/eTMR0_CH2/CAN0_RX/UART0_RX, 18 PTD_5/MPWM0_CH6/LPTMR0_ALT2/SCU_CLKOUT/TMU_IN7/SPI0_PCS1, 19 PTC_1/eTMR0_CH1/SPI2_SOUT/eTMR1_CH7, 20 PTC_16/eTMR1_FLT2, 21 PTC_15/eTMR1_CH3/SPI2_SCK/TMU_IN8, 22 PTC_14/eTMR1_CH2/SPI2_PCS0/TMU_IN9, 23 PTB_3/eTMR1_CH1/SPI0_SIN/eTMR1_QD_PHA/TMU_IN2, 24 PTB_2/eTMR1_CH0/SPI0_SCK/eTMR1_QD_PHB/TMU_IN3, 25 PTB_1/UART0_TX/SPI0_SOUT/TCLK_IN0/CAN0_TX/LPTMR0_ALT1, 26 PTB_0/UART0_RX/SPI0_PCS0/LPTMR0_ALT3/CAN0_RX, 27 PTC_9/UART1_TX/eTMR1_FLT1/eTMR0_FLT1/UART0_RTS, 28 PTC_8/UART1_RX/eTMR1_FLT0/UART0_CTS, 29 PTA_7/eTMR0_FLT2/SPI1_PCS3/UART1_RTS, 30 VSS, 31 VDD, 32 PTB_13/eTMR0_CH1/UART1_CTS, 33 PTD_3/MPWM0_CH5/SPI1_PCS0/I2C1_SCL/UART1_TX/TMU_IN4/CM33_NMI_b, 34 PTD_2/MPWM0_CH4/SPI1_SOUT/I2C1_SDA/UART1_RX/TMU_IN5, 35 PTA_3/MPWM0_CH1/I2C0_SCL/EWDG_IN/SPI2_SCK/UART0_TX, 36 PTA_2/MPWM0_CH0/I2C0_SDA/EWDG_OUT_b/SPI2_SIN/UART0_RX, 37 PTA_1/eTMR1_CH1/SPI2_SOUT/eTMR1_QD_PHA/UART0_RTS/TMU_OUT0, 38 PTA_0/MPWM0_CH7/SPI2_PCS0/eTMR1_QD_PHA/UART0_CTS/TMU_OUT3, 39 PTC_7/UART1_TX/CAN1_TX/MPWM0_CH3/SPI2_PCS2/eTMR1_QD_PHA, 40 PTC_6/UART1_RX/CAN1_RX/MPWM0_CH2/SPI2_PCS3/eTMR1_QD_PHB, 41 PTA_13/eTMR1_CH7/CAN1_TX/UART2_TX, 42 PTA_12/eTMR1_CH6/CAN1_RX/UART2_RX, 43 PTA_11/eTMR1_CH5/ACMP0_ACTIVE/I2C1_SCL, 44 PTA_10/eTMR1_CH4/I2C1_SDA/JTAG_TDO_SWD_SWO, 45 PTC_5/MPWM0_CH4/JTAG_TDI, 46 PTC_4/eTMR1_CH0/EWDG_IN/eTMR1_QD_PHB/JTAG_TCK_SWD_CLK, 47 PTA_5/TCLK_IN1/eTMR1_QD_PHB/RCU_RESET_b, 48 PTA_4/ACMP0_OUT/EWDG_OUT_b/JTAG_TMS_SWD_IO

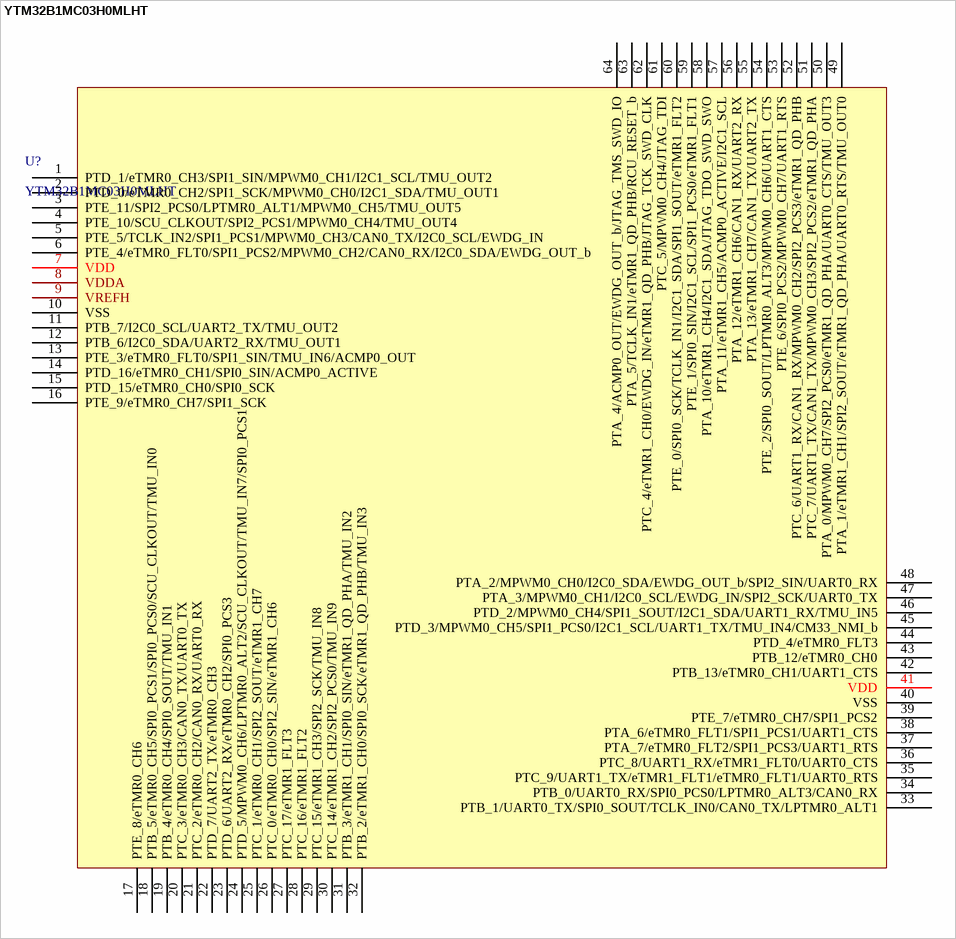
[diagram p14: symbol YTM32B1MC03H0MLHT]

## YTM32B1MC03H0MLHT
designator U?
B1M family  32-bit ARM Cortex-M33 MCU with 256K pflash and 32K SRAM, LQFP-64 package
footprint LQFP64 10x10_L
footprint LQFP64 10x10_M
footprint LQFP64 10x10_N
pins: 1 PTD_1/eTMR0_CH3/SPI1_SIN/MPWM0_CH1/I2C1_SCL/TMU_OUT2, 2 PTD_0/eTMR0_CH2/SPI1_SCK/MPWM0_CH0/I2C1_SDA/TMU_OUT1, 3 PTE_11/SPI2_PCS0/LPTMR0_ALT1/MPWM0_CH5/TMU_OUT5, 4 PTE_10/SCU_CLKOUT/SPI2_PCS1/MPWM0_CH4/TMU_OUT4, 5 PTE_5/TCLK_IN2/SPI1_PCS1/MPWM0_CH3/CAN0_TX/I2C0_SCL/EWDG_IN, 6 PTE_4/eTMR0_FLT0/SPI1_PCS2/MPWM0_CH2/CAN0_RX/I2C0_SDA/EWDG_OUT_b, 7 VDD, 8 VDDA, 9 VREFH, 10 VSS, 11 PTB_7/I2C0_SCL/UART2_TX/TMU_OUT2, 12 PTB_6/I2C0_SDA/UART2_RX/TMU_OUT1, 13 PTE_3/eTMR0_FLT0/SPI1_SIN/TMU_IN6/ACMP0_OUT, 14 PTD_16/eTMR0_CH1/SPI0_SIN/ACMP0_ACTIVE, 15 PTD_15/eTMR0_CH0/SPI0_SCK, 16 PTE_9/eTMR0_CH7/SPI1_SCK, 17 PTE_8/eTMR0_CH6, 18 PTB_5/eTMR0_CH5/SPI0_PCS1/SPI0_PCS0/SCU_CLKOUT/TMU_IN0, 19 PTB_4/eTMR0_CH4/SPI0_SOUT/TMU_IN1, 20 PTC_3/eTMR0_CH3/CAN0_TX/UART0_TX, 21 PTC_2/eTMR0_CH2/CAN0_RX/UART0_RX, 22 PTD_7/UART2_TX/eTMR0_CH3, 23 PTD_6/UART2_RX/eTMR0_CH2/SPI0_PCS3, 24 PTD_5/MPWM0_CH6/LPTMR0_ALT2/SCU_CLKOUT/TMU_IN7/SPI0_PCS1, 25 PTC_1/eTMR0_CH1/SPI2_SOUT/eTMR1_CH7, 26 PTC_0/eTMR0_CH0/SPI2_SIN/eTMR1_CH6, 27 PTC_17/eTMR1_FLT3, 28 PTC_16/eTMR1_FLT2, 29 PTC_15/eTMR1_CH3/SPI2_SCK/TMU_IN8, 30 PTC_14/eTMR1_CH2/SPI2_PCS0/TMU_IN9, 31 PTB_3/eTMR1_CH1/SPI0_SIN/eTMR1_QD_PHA/TMU_IN2, 32 PTB_2/eTMR1_CH0/SPI0_SCK/eTMR1_QD_PHB/TMU_IN3, 33 PTB_1/UART0_TX/SPI0_SOUT/TCLK_IN0/CAN0_TX/LPTMR0_ALT1, 34 PTB_0/UART0_RX/SPI0_PCS0/LPTMR0_ALT3/CAN0_RX, 35 PTC_9/UART1_TX/eTMR1_FLT1/eTMR0_FLT1/UART0_RTS, 36 PTC_8/UART1_RX/eTMR1_FLT0/UART0_CTS, 37 PTA_7/eTMR0_FLT2/SPI1_PCS3/UART1_RTS, 38 PTA_6/eTMR0_FLT1/SPI1_PCS1/UART1_CTS, 39 PTE_7/eTMR0_CH7/SPI1_PCS2, 40 VSS, 41 VDD, 42 PTB_13/eTMR0_CH1/UART1_CTS, 43 PTB_12/eTMR0_CH0, 44 PTD_4/eTMR0_FLT3, 45 PTD_3/MPWM0_CH5/SPI1_PCS0/I2C1_SCL/UART1_TX/TMU_IN4/CM33_NMI_b, 46 PTD_2/MPWM0_CH4/SPI1_SOUT/I2C1_SDA/UART1_RX/TMU_IN5, 47 PTA_3/MPWM0_CH1/I2C0_SCL/EWDG_IN/SPI2_SCK/UART0_TX, 48 PTA_2/MPWM0_CH0/I2C0_SDA/EWDG_OUT_b/SPI2_SIN/UART0_RX, 49 PTA_1/eTMR1_CH1/SPI2_SOUT/eTMR1_QD_PHA/UART0_RTS/TMU_OUT0, 50 PTA_0/MPWM0_CH7/SPI2_PCS0/eTMR1_QD_PHA/UART0_CTS/TMU_OUT3, 51 PTC_7/UART1_TX/CAN1_TX/MPWM0_CH3/SPI2_PCS2/eTMR1_QD_PHA, 52 PTC_6/UART1_RX/CAN1_RX/MPWM0_CH2/SPI2_PCS3/eTMR1_QD_PHB, 53 PTE_6/SPI0_PCS2/MPWM0_CH7/UART1_RTS, 54 PTE_2/SPI0_SOUT/LPTMR0_ALT3/MPWM0_CH6/UART1_CTS, 55 PTA_13/eTMR1_CH7/CAN1_TX/UART2_TX, 56 PTA_12/eTMR1_CH6/CAN1_RX/UART2_RX, 57 PTA_11/eTMR1_CH5/ACMP0_ACTIVE/I2C1_SCL, 58 PTA_10/eTMR1_CH4/I2C1_SDA/JTAG_TDO_SWD_SWO, 59 PTE_1/SPI0_SIN/I2C1_SCL/SPI1_PCS0/eTMR1_FLT1, 60 PTE_0/SPI0_SCK/TCLK_IN1/I2C1_SDA/SPI1_SOUT/eTMR1_FLT2, 61 PTC_5/MPWM0_CH4/JTAG_TDI, 62 PTC_4/eTMR1_CH0/EWDG_IN/eTMR1_QD_PHB/JTAG_TCK_SWD_CLK, 63 PTA_5/TCLK_IN1/eTMR1_QD_PHB/RCU_RESET_b, 64 PTA_4/ACMP0_OUT/EWDG_OUT_b/JTAG_TMS_SWD_IO

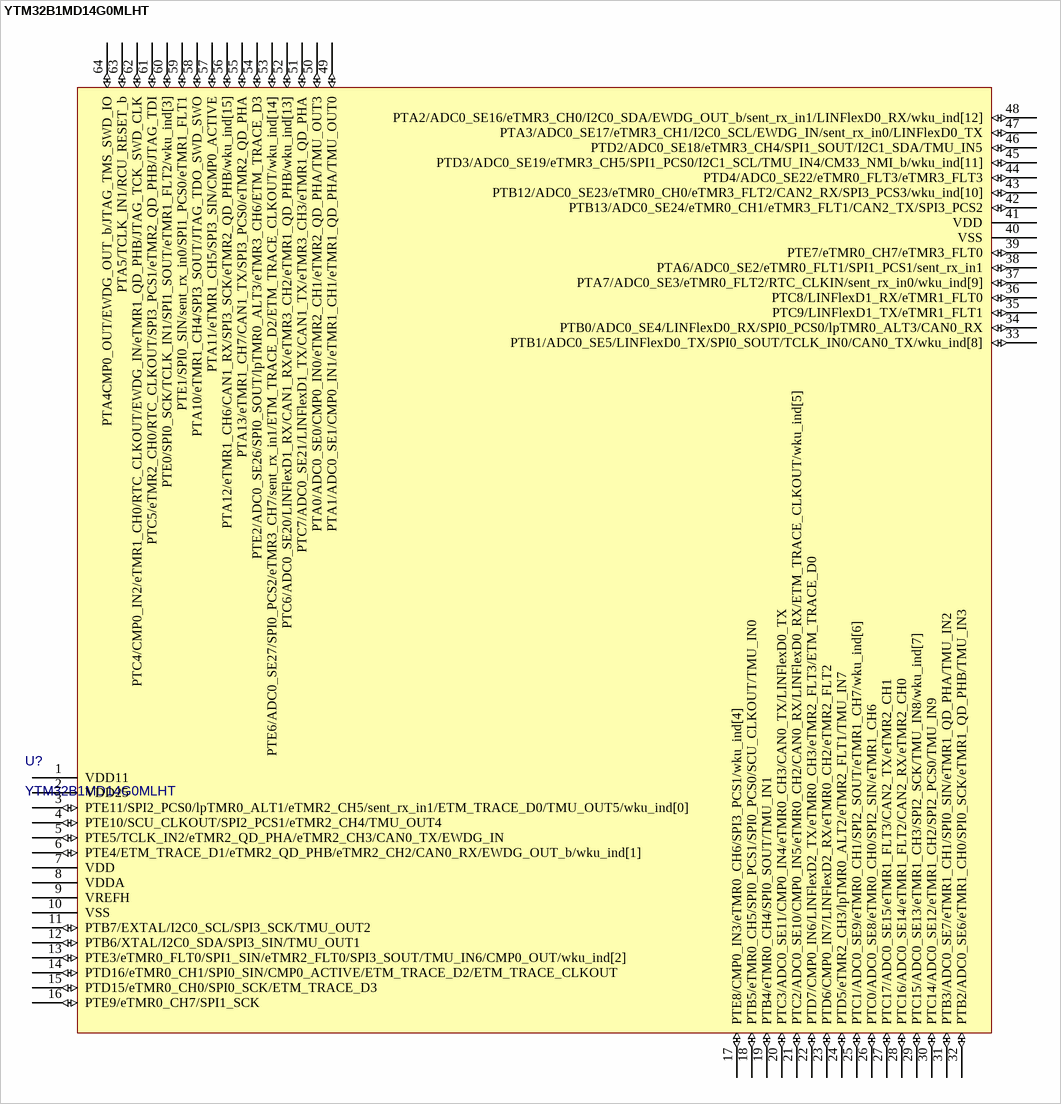
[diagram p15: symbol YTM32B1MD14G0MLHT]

## YTM32B1MD14G0MLHT
designator U?
B1M family  32-bit ARM Cortex-M33 MCU with 512K pflash and 128K SRAM, LQFP-64 package
footprint LQFP64 10x10_L
footprint LQFP64 10x10_M
footprint LQFP64 10x10_N
pins: 1 VDD11, 2 VDD25, 3 PTE11/SPI2_PCS0/lpTMR0_ALT1/eTMR2_CH5/sent_rx_in1/ETM_TRACE_D0/TMU_OUT5/wku_ind[0] (io), 4 PTE10/SCU_CLKOUT/SPI2_PCS1/eTMR2_CH4/TMU_OUT4 (io), 5 PTE5/TCLK_IN2/eTMR2_QD_PHA/eTMR2_CH3/CAN0_TX/EWDG_IN (io), 6 PTE4/ETM_TRACE_D1/eTMR2_QD_PHB/eTMR2_CH2/CAN0_RX/EWDG_OUT_b/wku_ind[1] (io), 7 VDD, 8 VDDA, 9 VREFH, 10 VSS, 11 PTB7/EXTAL/I2C0_SCL/SPI3_SCK/TMU_OUT2 (io), 12 PTB6/XTAL/I2C0_SDA/SPI3_SIN/TMU_OUT1 (io), 13 PTE3/eTMR0_FLT0/SPI1_SIN/eTMR2_FLT0/SPI3_SOUT/TMU_IN6/CMP0_OUT/wku_ind[2] (io), 14 PTD16/eTMR0_CH1/SPI0_SIN/CMP0_ACTIVE/ETM_TRACE_D2/ETM_TRACE_CLKOUT (io), 15 PTD15/eTMR0_CH0/SPI0_SCK/ETM_TRACE_D3 (io), 16 PTE9/eTMR0_CH7/SPI1_SCK (io), 17 PTE8/CMP0_IN3/eTMR0_CH6/SPI3_PCS1/wku_ind[4] (io), 18 PTB5/eTMR0_CH5/SPI0_PCS1/SPI0_PCS0/SCU_CLKOUT/TMU_IN0 (io), 19 PTB4/eTMR0_CH4/SPI0_SOUT/TMU_IN1 (io), 20 PTC3/ADC0_SE11/CMP0_IN4/eTMR0_CH3/CAN0_TX/LINFlexD0_TX (io), 21 PTC2/ADC0_SE10/CMP0_IN5/eTMR0_CH2/CAN0_RX/LINFlexD0_RX/ETM_TRACE_CLKOUT/wku_ind[5] (io), 22 PTD7/CMP0_IN6/LINFlexD2_TX/eTMR0_CH3/eTMR2_FLT3/ETM_TRACE_D0 (io), 23 PTD6/CMP0_IN7/LINFlexD2_RX/eTMR0_CH2/eTMR2_FLT2 (io), 24 PTD5/eTMR2_CH3/lpTMR0_ALT2/eTMR2_FLT1/TMU_IN7 (io), 25 PTC1/ADC0_SE9/eTMR0_CH1/SPI2_SOUT/eTMR1_CH7/wku_ind[6] (io), 26 PTC0/ADC0_SE8/eTMR0_CH0/SPI2_SIN/eTMR1_CH6 (io), 27 PTC17/ADC0_SE15/eTMR1_FLT3/CAN2_TX/eTMR2_CH1 (io), 28 PTC16/ADC0_SE14/eTMR1_FLT2/CAN2_RX/eTMR2_CH0 (io), 29 PTC15/ADC0_SE13/eTMR1_CH3/SPI2_SCK/TMU_IN8/wku_ind[7] (io), 30 PTC14/ADC0_SE12/eTMR1_CH2/SPI2_PCS0/TMU_IN9 (io), 31 PTB3/ADC0_SE7/eTMR1_CH1/SPI0_SIN/eTMR1_QD_PHA/TMU_IN2 (io), 32 PTB2/ADC0_SE6/eTMR1_CH0/SPI0_SCK/eTMR1_QD_PHB/TMU_IN3 (io), 33 PTB1/ADC0_SE5/LINFlexD0_TX/SPI0_SOUT/TCLK_IN0/CAN0_TX/wku_ind[8] (io), 34 PTB0/ADC0_SE4/LINFlexD0_RX/SPI0_PCS0/lpTMR0_ALT3/CAN0_RX (io), 35 PTC9/LINFlexD1_TX/eTMR1_FLT1 (io), 36 PTC8/LINFlexD1_RX/eTMR1_FLT0 (io), 37 PTA7/ADC0_SE3/eTMR0_FLT2/RTC_CLKIN/sent_rx_in0/wku_ind[9] (io), 38 PTA6/ADC0_SE2/eTMR0_FLT1/SPI1_PCS1/sent_rx_in1 (io), 39 PTE7/eTMR0_CH7/eTMR3_FLT0 (io), 40 VSS, 41 VDD, 42 PTB13/ADC0_SE24/eTMR0_CH1/eTMR3_FLT1/CAN2_TX/SPI3_PCS2 (io), 43 PTB12/ADC0_SE23/eTMR0_CH0/eTMR3_FLT2/CAN2_RX/SPI3_PCS3/wku_ind[10] (io), 44 PTD4/ADC0_SE22/eTMR0_FLT3/eTMR3_FLT3 (io), 45 PTD3/ADC0_SE19/eTMR3_CH5/SPI1_PCS0/I2C1_SCL/TMU_IN4/CM33_NMI_b/wku_ind[11] (io), 46 PTD2/ADC0_SE18/eTMR3_CH4/SPI1_SOUT/I2C1_SDA/TMU_IN5 (io), 47 PTA3/ADC0_SE17/eTMR3_CH1/I2C0_SCL/EWDG_IN/sent_rx_in0/LINFlexD0_TX (io), 48 PTA2/ADC0_SE16/eTMR3_CH0/I2C0_SDA/EWDG_OUT_b/sent_rx_in1/LINFlexD0_RX/wku_ind[12] (io), 49 PTA1/ADC0_SE1/CMP0_IN1/eTMR1_CH1/eTMR1_QD_PHA/TMU_OUT0 (io), 50 PTA0/ADC0_SE0/CMP0_IN0/eTMR2_CH1/eTMR2_QD_PHA/TMU_OUT3 (io), 51 PTC7/ADC0_SE21/LINFlexD1_TX/CAN1_TX/eTMR3_CH3/eTMR1_QD_PHA (io), 52 PTC6/ADC0_SE20/LINFlexD1_RX/CAN1_RX/eTMR3_CH2/eTMR1_QD_PHB/wku_ind[13] (io), 53 PTE6/ADC0_SE27/SPI0_PCS2/eTMR3_CH7/sent_rx_in1/ETM_TRACE_D2/ETM_TRACE_CLKOUT/wku_ind[14] (io), 54 PTE2/ADC0_SE26/SPI0_SOUT/lpTMR0_ALT3/eTMR3_CH6/ETM_TRACE_D3 (io), 55 PTA13/eTMR1_CH7/CAN1_TX/SPI3_PCS0/eTMR2_QD_PHA (io), 56 PTA12/eTMR1_CH6/CAN1_RX/SPI3_SCK/eTMR2_QD_PHB/wku_ind[15] (io), 57 PTA11/eTMR1_CH5/SPI3_SIN/CMP0_ACTIVE (io), 58 PTA10/eTMR1_CH4/SPI3_SOUT/JTAG_TDO_SWD_SWO (io), 59 PTE1/SPI0_SIN/sent_rx_in0/SPI1_PCS0/eTMR1_FLT1 (io), 60 PTE0/SPI0_SCK/TCLK_IN1/SPI1_SOUT/eTMR1_FLT2/wku_ind[3] (io), 61 PTC5/eTMR2_CH0/RTC_CLKOUT/SPI3_PCS1/eTMR2_QD_PHB/JTAG_TDI (io), 62 PTC4/CMP0_IN2/eTMR1_CH0/RTC_CLKOUT/EWDG_IN/eTMR1_QD_PHB/JTAG_TCK_SWD_CLK (io), 63 PTA5/TCLK_IN1/RCU_RESET_b (io), 64 PTA4CMP0_OUT/EWDG_OUT_b/JTAG_TMS_SWD_IO (io)

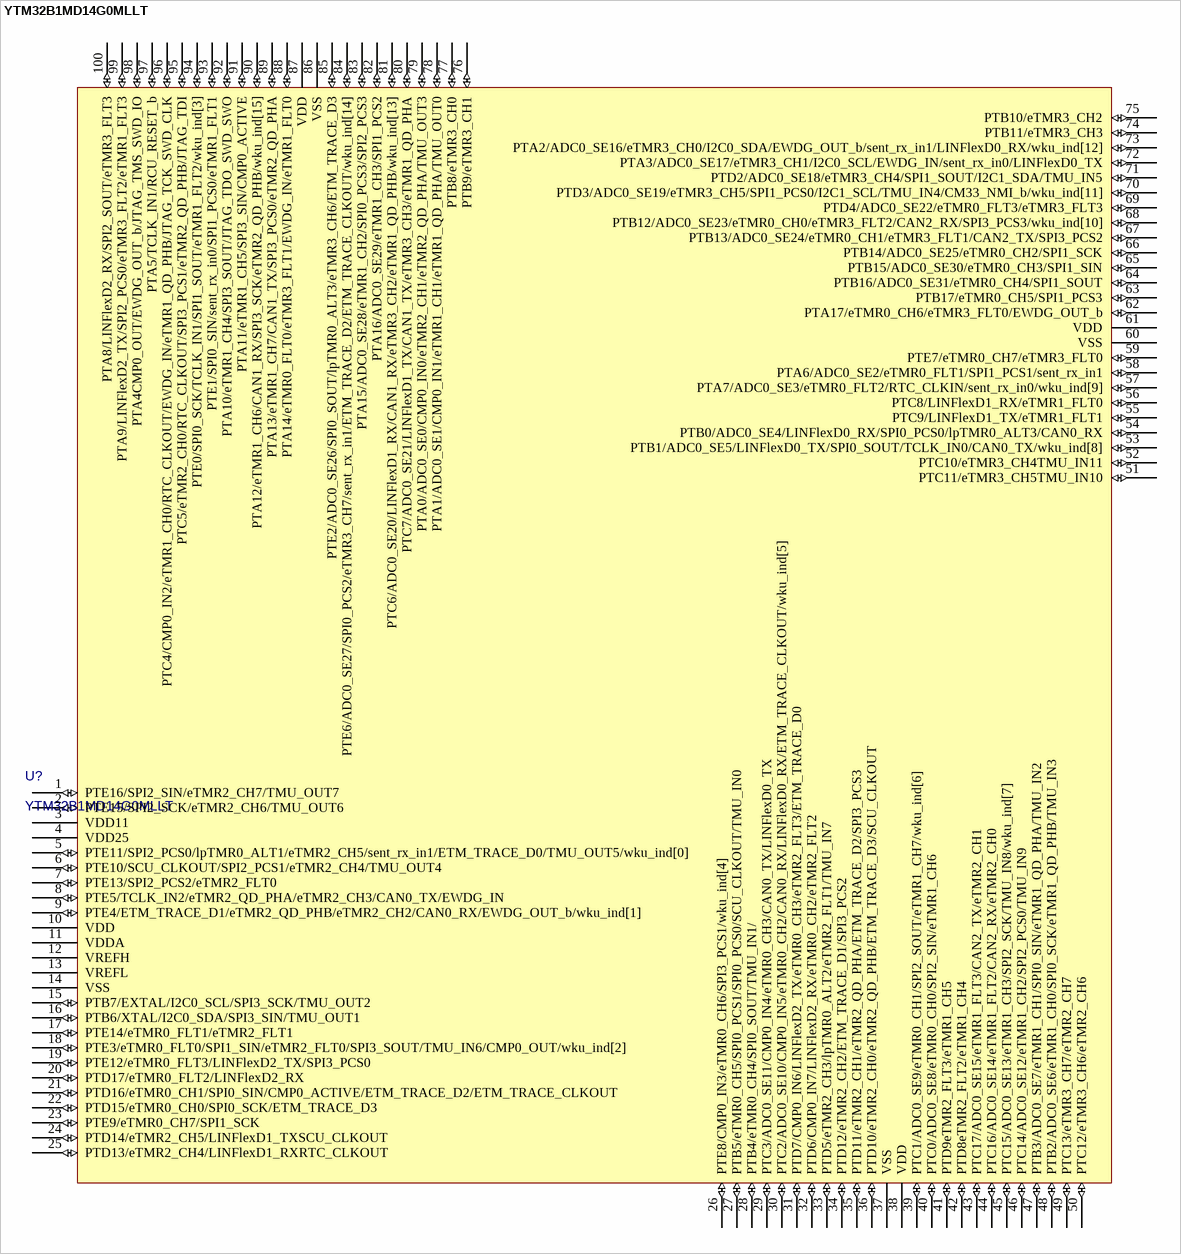
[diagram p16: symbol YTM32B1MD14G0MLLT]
